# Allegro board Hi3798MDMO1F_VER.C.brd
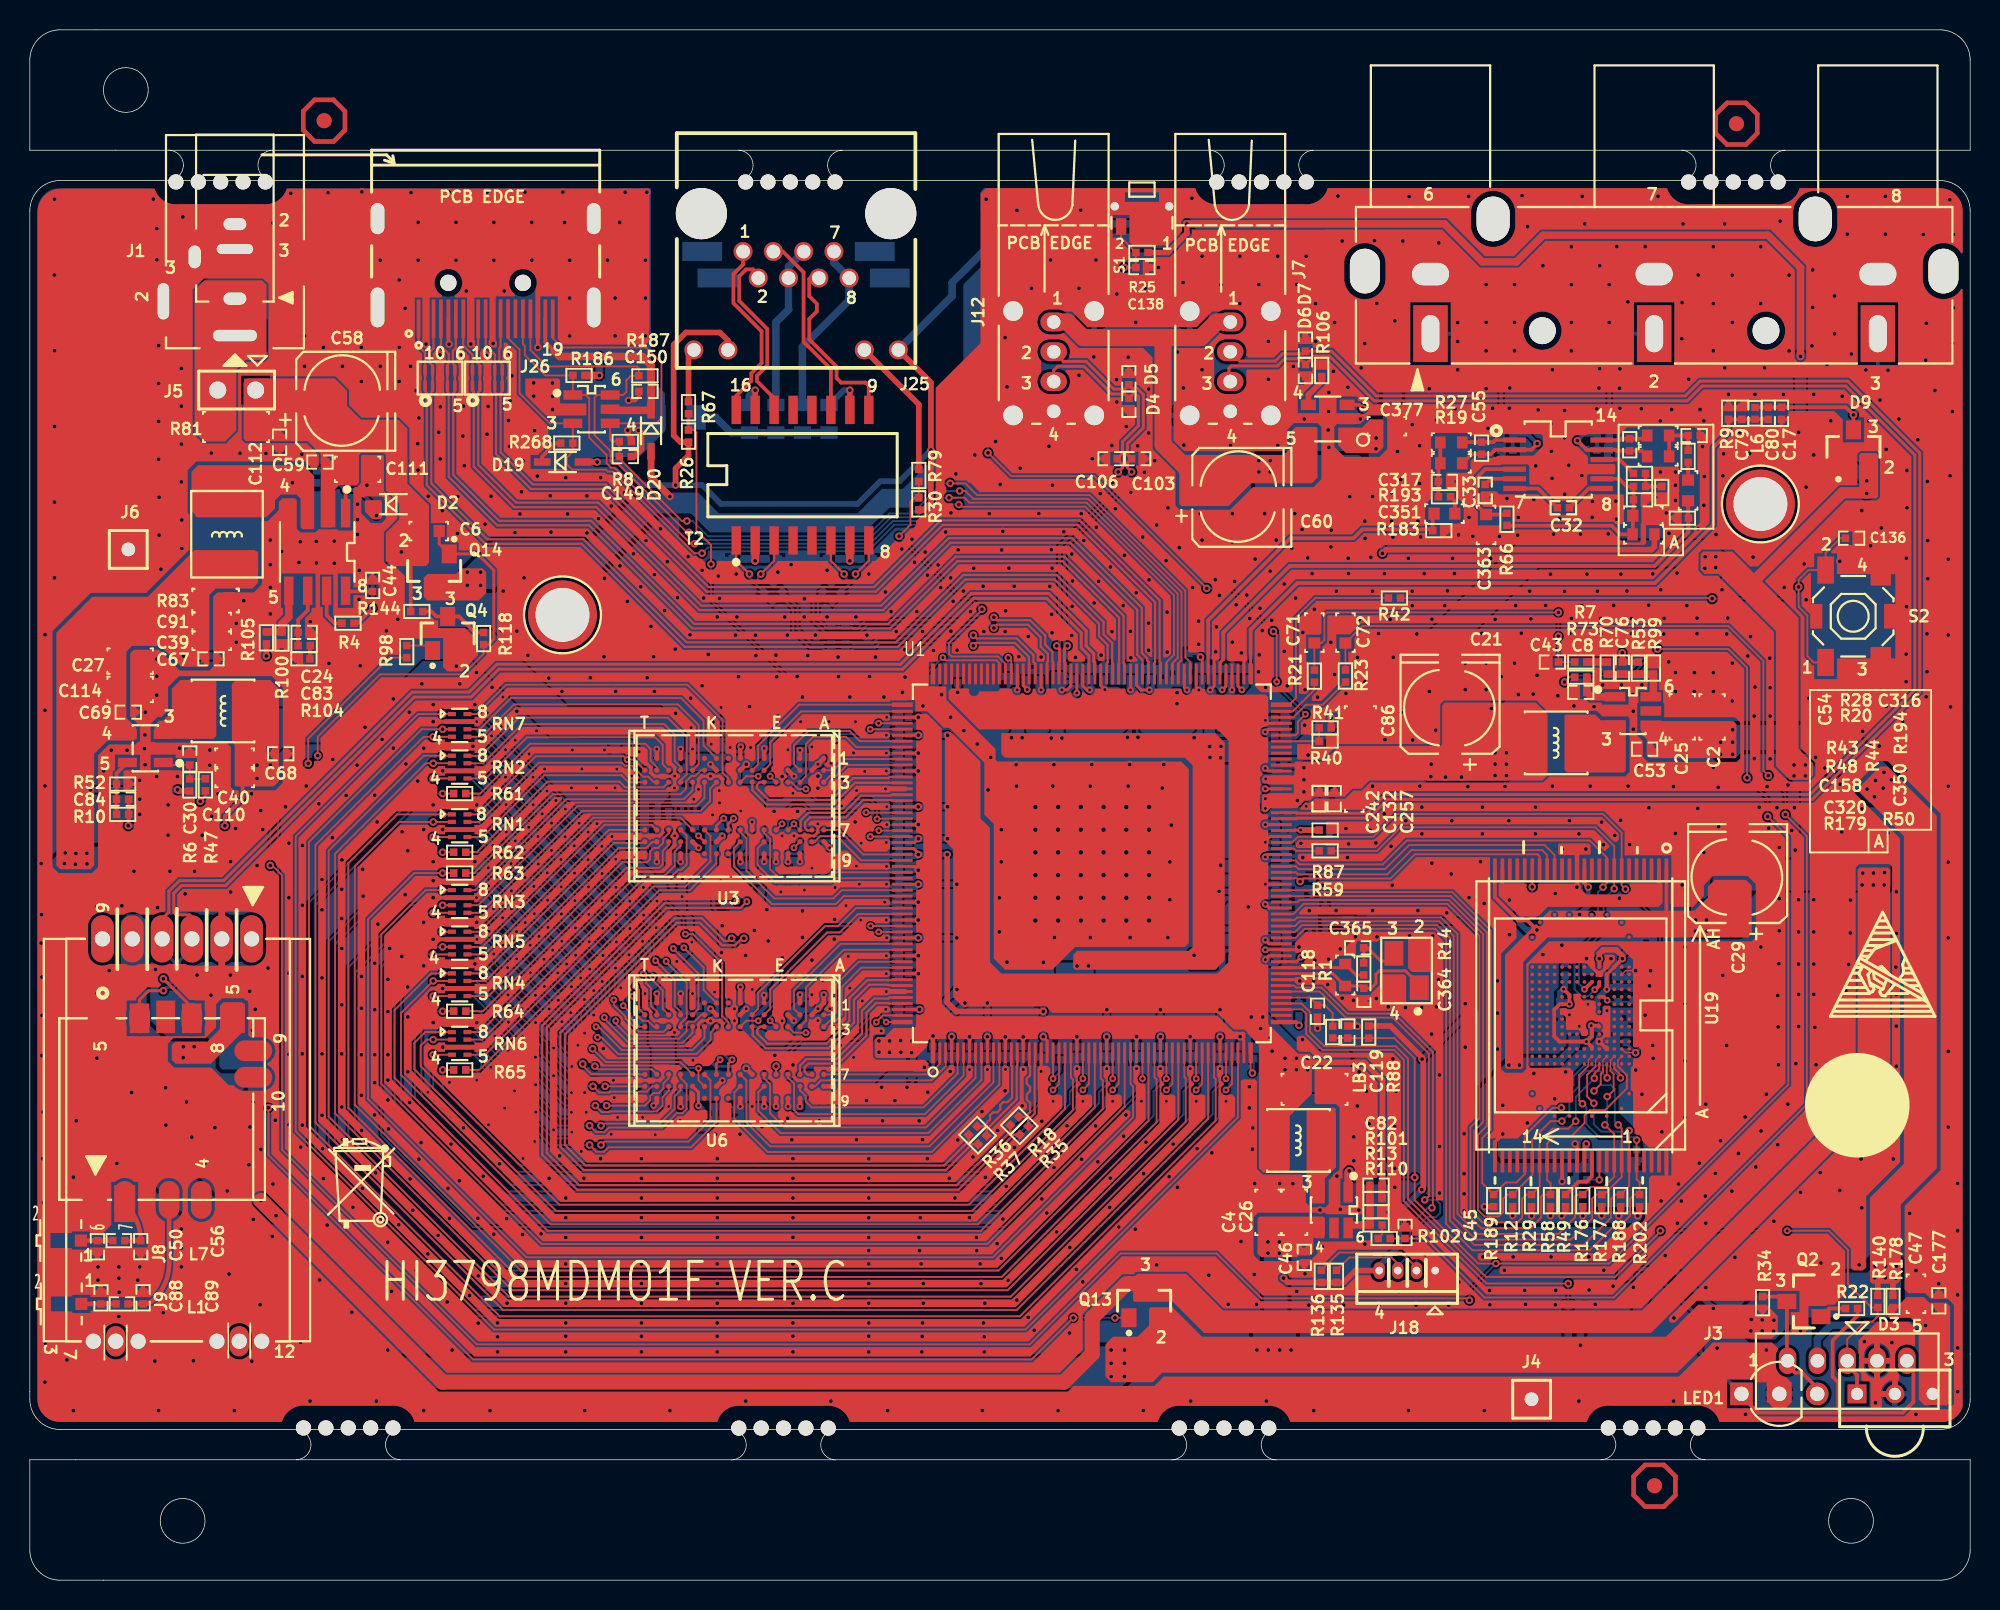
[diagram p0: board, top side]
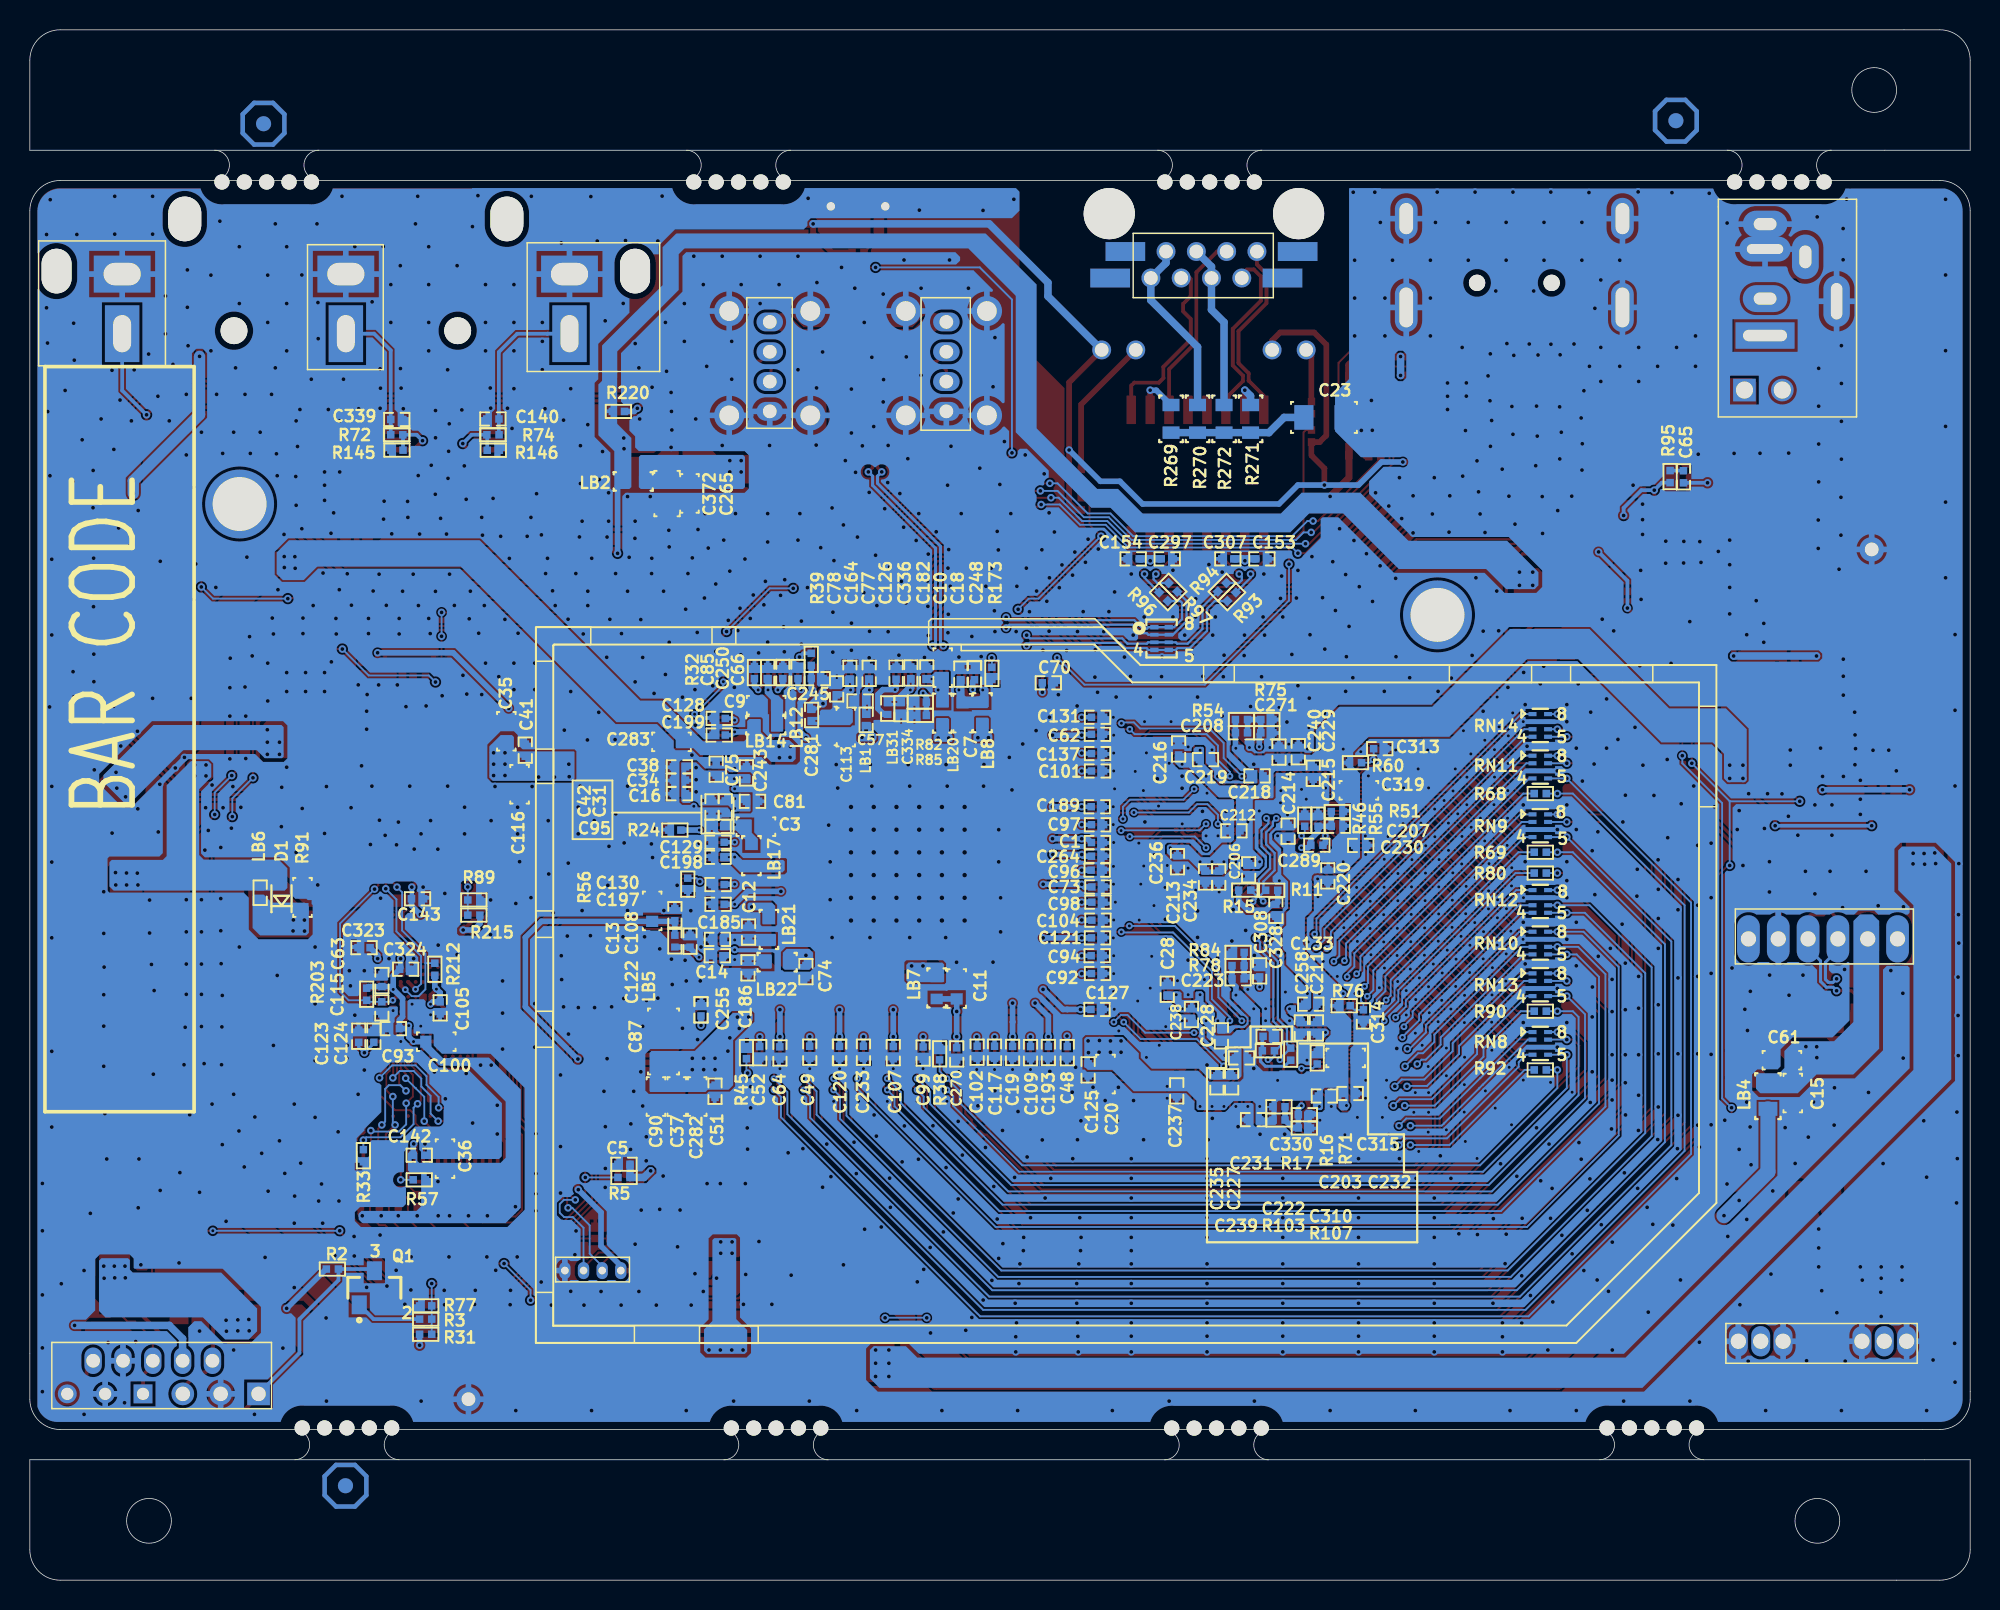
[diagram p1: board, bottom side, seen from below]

Outline 130.13 x 104.03 mm; copper layers: TOP, BOTTOM. Coordinates in mm from the lower left corner of the outline.
Outline path: circle c6.44,99.99 r1.5 ; circle c10.25,3.98 r1.5 ; circle c122.14,3.98 r1.5 ; 0,102 arc(0.6,103.44) 2.03,104.03 128.1,104.03 arc(129.53,103.44) 130.13,102 130.13,95.95 0,95.95 0,102 ; 0,91.89 arc(0.6,93.33) 2.03,93.92 128.1,93.92 arc(129.53,93.33) 130.13,91.89 130.13,12.14 arc(129.53,10.71) 128.1,10.11 2.03,10.11 arc(0.6,10.71) 0,12.14 0,91.89 ; 0,8.08 130.13,8.08 130.13,2.03 arc(129.53,0.6) 128.1,0 2.03,0 arc(0.6,0.6) 0,2.03 0,8.08

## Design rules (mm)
constraint set DEFAULT: min track width 0.127
net group $4N904: nets $4N904 $4N905
net group $6N188: nets $6N188 XOUT
net group $6N2411: nets $6N2411 USB_BOOT
net group $8N1694: nets $8N1694 DDR_CLK0P
net group $8N1695: nets $8N1695 DDR_CLK0N
net group $8N1696: nets $8N1696 DDR_CLK1P
net group $8N1697: nets $8N1697 DDR_CLK1N
net group $13N803: nets 5V0_MOS $13N803
net group $14N721: nets $14N721 LED_RED
net group $14N731: nets $14N731 LED_CTRL
net group $15N1021: nets $15N1021 $15N1025
net group $15N1022: nets $15N1022 $15N1029
net group $15N1031: nets $15N1031 $15N1032
net group $15N1036: nets $15N1036 $15N1037
net group $16N1066: nets $16N1066 LED0_BASE
net group $16N1067: nets $16N1067 LED0_LINK_ACT
net group $18N796: nets $18N796 HDMI_TX_CEC
net group CLK: nets NF_RDY0_EMMC_RST NF_REN_EMMC_CLK
net group CVBS: nets CVBS CVBS_OUT
net group DIFF: nets TX+_PHY0 TX-_PHY0
net group DIFF90: nets USB2_DM USB2_DP
net group DIFFPAIR1: nets RX+_PHY0 RX-_PHY0
net group 01: nets ADAC_VOUTL ADAC_VOUTR AUDIO_L AUDIO_R
net group 5V0_MOS_HDMI: nets 5V0_MOS_HDMI HDMI_TX_SCL HDMI_TX_SDA
net group $4N593: nets $4N593 $4N687 $4N724 $5N549 STANDBY_PWROFF
net group $4N676: nets 1V1_CPU $4N676 $4N677 $4N894 CPU_CTRL
net group $4N714: nets $4N714 $4N715 $4N716 CORE_CTRL
net group $4N903: nets $4N903 $4N923 $4N925
net group $4N906: nets 5V0 $4N906 $4N944 $5N541 $5N542
net group $15N1074: nets $15N1074 $15N1075 $15N1114 VDD_AUDIO
net group DDR-ADD: nets DDR_ADDR0 DDR_ADDR0_A DDR_ADDR0_B DDR_ADDR1 DDR_ADDR1_A DDR_ADDR1_B DDR_ADDR2 DDR_ADDR2_A DDR_ADDR2_B DDR_ADDR3 DDR_ADDR3_A DDR_ADDR3_B DDR_ADDR4 DDR_ADDR4_A DDR_ADDR4_B DDR_ADDR5 DDR_ADDR5_A DDR_ADDR5_B DDR_ADDR6 DDR_ADDR6_A DDR_ADDR6_B DDR_ADDR7 DDR_ADDR7_A DDR_ADDR7_B DDR_ADDR8 DDR_ADDR8_A DDR_ADDR8_B DDR_ADDR9 DDR_ADDR9_A DDR_ADDR9_B DDR_ADDR10 DDR_ADDR10_A DDR_ADDR10_B DDR_ADDR11 DDR_ADDR11_A DDR_ADDR11_B DDR_ADDR12 DDR_ADDR12_A DDR_ADDR12_B DDR_ADDR13 DDR_ADDR13_A DDR_ADDR13_B DDR_ADDR14 DDR_ADDR14_A DDR_ADDR14_B DDR_ADDR15 DDR_ADDR15_A DDR_ADDR15_B DDR_BA0 DDR_BA0_A DDR_BA0_B DDR_BA1 DDR_BA1_A DDR_BA1_B DDR_BA2 DDR_BA2_A DDR_BA2_B DDR_CASN DDR_CASN_A DDR_CASN_B DDR_CKE DDR_CKE_A DDR_CKE_B DDR_CSN DDR_CSN_A DDR_CSN_B DDR_ODT DDR_ODT_A DDR_ODT_B DDR_PLL DDR_RASN DDR_RASN_A DDR_RASN_B DDR_RESETN DDR_RESETN_A DDR_RESETN_B DDR_VREF_CA_A DDR_VREF_CA_B DDR_VREF_DQ_A DDR_VREF_DQ_B DDR_WEN DDR_WEN_A DDR_WEN_B
net group DDR-DATA: nets DDR_DM0 DDR_DM1 DDR_DM2 DDR_DM3 DDR_DQ0 DDR_DQ1 DDR_DQ2 DDR_DQ3 DDR_DQ4 DDR_DQ5 DDR_DQ6 DDR_DQ7 DDR_DQ8 DDR_DQ9 DDR_DQ10 DDR_DQ11 DDR_DQ12 DDR_DQ13 DDR_DQ14 DDR_DQ15 DDR_DQ16 DDR_DQ17 DDR_DQ18 DDR_DQ19 DDR_DQ20 DDR_DQ21 DDR_DQ22 DDR_DQ23 DDR_DQ24 DDR_DQ25 DDR_DQ26 DDR_DQ27 DDR_DQ28 DDR_DQ29 DDR_DQ30 DDR_DQ31
net group DIFF100: nets HDMI_TX0N HDMI_TX0P HDMI_TX1N HDMI_TX1P HDMI_TX2N HDMI_TX2P HDMI_TXCN HDMI_TXCP
net group DQS: nets DDR_DQS0N DDR_DQS0P DDR_DQS1N DDR_DQS1P DDR_DQS3N DDR_DQS3P
net group GND: nets GND
net group POWER: nets 1V1_CORE 1V5_DDR3 3V3 3V3_MOS
net group USB: nets USB0_DM USB0_DP USB1_DM USB1_DP

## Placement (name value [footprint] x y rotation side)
C1  100NF  [SC0402]  58.53 49.5 180 bottom
C2  10UF  [SC0805]  112.82 57.93 90 top
C3  1UF  [SC0603]  81.43 50.56 180 bottom
C4  10UF  [SC0805]  83.04 24.68 90 top
C5  220NF  [SC0402]  90.28 27.91 0 bottom
C6  220NF  [SC0603]  26.75 70.39 0 top
C7  1UF  [SC0603]  67.56 58.18 270 bottom
C8  220NF  [SC0402]  104.01 59.58 180 top
C9  1UF  [SC0603]  80.75 58.72 0 bottom
C10  1UF  [SC0603]  68.91 61.23 90 bottom
C11  1UF  [SC0603]  67.97 39.7 90 bottom
C12  1UF  [SC0402]  81.93 43.49 90 bottom
C13  1UF  [SC0603]  88.39 44.91 90 bottom
C14  1UF  [SC0402]  84.02 41.9 0 bottom
C15  10UF  [SC0603]  11.9 32.69 270 bottom
C16  100NF  [SC0402]  86.56 52.77 0 bottom
C17  180PF  [SC0402]  117.48 78.3 270 top
C18  10NF/NC  [SC0402]  67.69 60.8 90 bottom
C19  470NF  [SC0402]  64.22 35.41 270 bottom
C20  10UF/NC  [SC0603]  57.99 33.96 270 bottom
C21  100UF  [SAC6666]  95.25 58.78 90 top
C22  47UF/NC  [SC1206]  86.16 32.94 0 top
C23  1NF  [SC1206]  43.34 78.02 180 bottom
C24  47PF/NC  [SC0402]  18.4 63.6 0 top
C25  10UF  [SC0805]  110.81 57.93 90 top
C26  10UF/NC  [SC0805]  84.82 24.68 90 top
C27  10UF/NC  [SC0805]  6.73 61.67 0 top
C28  100NF  [SC0402]  53.85 39.65 90 bottom
C29  100UF/NC  [SAC6666]  114.53 47.42 90 top
C30  220NF  [SC0402]  10.73 55.11 90 top
C31  2.2UF  [HSC0402]  83.49 51.88 270 bottom
C32  330N  [HSC0402]  102.85 71.96 0 top
C33  330N  [HSC0402]  97.6 73.12 90 top
C34  100NF  [SC0402]  86.56 53.69 0 bottom
C35  10UF  [SC0603]  98.17 56.96 90 bottom
C36  1UF/NC  [SC0603]  102.29 28.29 90 bottom
C37  10UF  [SC0603]  86.74 32.45 270 bottom
C38  100NF  [SC0402]  86.56 54.58 0 bottom
C39  10UF  [SC0603]  12.2 63.03 0 top
C40  10UF  [SC0603]  13.73 55.19 180 top
C41  100NF  [SC0402]  96.9 55.69 90 bottom
C42  100NF  [SC0402]  84.38 51.88 270 bottom
C43  100NF/NC  [SC0402]  102.11 61.61 180 top
C44  100NF  [SC0402]  22.99 66.75 90 top
C45  100NF/NC  [SC0402]  92.23 23.34 90 top
C46  100NF  [SC0402]  85.47 21.66 270 top
C47  10UF  [SC0603]  126.49 19.22 90 top
C48  100NF  [SC0402]  60.55 35.4 270 bottom
C49  100NF  [SC0402]  77.83 35.43 270 bottom
C50  1PF/NC  [SC0402]  4.53 22.38 270 top
C51  100NF  [SC0402]  84.18 32.81 270 bottom
C52  100NF  [SC0402]  81.18 35.4 270 bottom
C53  100NF  [SC0402]  108.3 55.76 180 top
C54  47PF  [SC0402]  107.29 76.19 90 top
C55  47PF  [SC0402]  97.36 75.96 270 top
C56  1PF/NC  [SC0402]  7.44 22.38 270 top
C57  100NF/NC  [SC0402]  74.45 59 0 bottom
C58  100UF  [SAC6666]  21.18 79.11 0 top
C59  100NF  [SC0402]  19.46 75.03 180 top
C60  100UF  [SAC6666]  81.28 72.66 0 top
C61  100NF  [SC0603]  12.62 34.89 0 bottom
C62  100NF  [SC0402]  58.53 56.76 180 bottom
C63  100NF/NC  [SC0402]  106.51 40.24 90 bottom
C64  100NF  [SC0402]  79.82 35.38 270 bottom
C65  10NF  [SC0402]  19.23 74.04 270 bottom
C66  100NF  [SC0402]  78.61 60.9 90 bottom
C67  100NF  [SC0402]  12.15 61.83 0 top
C68  100NF  [SC0402]  16.83 55.46 0 top
C69  100NF  [SC0402]  6.6 58.24 0 top
C70  100NF  [SC0402]  61.82 60.22 180 bottom
C71  2.2UF  [SC0603]  86.15 63.59 90 top
C72  2.2UF  [SC0603]  88.23 63.59 90 top
C73  100NF  [SC0402]  58.5 46.52 180 bottom
C74  100NF/NC  [SC0402]  78.08 40.84 270 bottom
C75  100NF  [SC0402]  84.1 54.42 90 bottom
C76  22PF  [SC0402]  106.8 61.2 90 top
C77  1UF  [SC0402]  73.84 60.85 90 bottom
C78  100NF/NC  [SC0402]  76.02 59.81 90 bottom
C79  180PF  [SC0402]  114.81 78.3 90 top
C80  100PF  [SC0402]  116.59 78.3 90 top
C81  100NF  [SC0402]  81.66 52.27 180 bottom
C82  22PF  [SC0402]  90.28 26.5 0 top
C83  3.3NF  [SC0402]  18.4 62.72 0 top
C84  22PF  [SC0402]  6.22 52.4 0 top
C85  100NF/NC  [SC0402]  80.65 60.9 90 bottom
C86  22UF/NC  [SC1206]  89.23 56.43 90 top
C87  22UF/NC  [SC1206]  87.63 36.15 90 bottom
C88  1PF/NC  [SC0402]  4.77 18.94 90 top
C89  1PF/NC  [SC0402]  7.6 18.95 90 top
C90  10UF  [SC0603]  88.14 32.45 270 bottom
C91  10UF  [SC0603]  12.2 64.3 0 top
C92  1UF  [SC0402]  58.52 40.71 180 bottom
C93  100NF/NC  [SC0402]  105.75 37.01 0 bottom
C94  1UF/NC  [SC0402]  58.55 41.9 180 bottom
C95  100NF/NC  [SC0402]  83.97 50.59 0 bottom
C96  1UF  [SC0402]  58.55 47.65 180 bottom
C97  470NF  [SC0402]  58.52 50.69 180 bottom
C98  100NF  [SC0402]  58.5 45.5 180 bottom
C99  100NF/NC  [SC0402]  70.22 35.37 270 bottom
C100  2.2UF  [SC0603]  102.87 36.14 180 bottom
C101  100NF  [SC0402]  58.52 54.3 180 bottom
C102  100NF  [SC0402]  66.6 35.43 270 bottom
C103  3PF/NC  [SC0402]  74.3 75.25 0 top
C104  100NF  [SC0402]  58.5 44.29 180 bottom
C105  100NF  [SC0402]  102.61 38.4 270 bottom
C106  3PF/NC  [SC0402]  72.52 75.25 180 top
C107  100NF  [SC0402]  72.22 35.4 270 bottom
C108  100NF/NC  [SC0402]  86.87 44.66 90 bottom
C109  470NF  [SC0402]  63.02 35.4 270 bottom
C110  10UF  [SC0603]  13.74 53.83 180 top
C111  10UF  [SC0805]  21.98 74.54 0 top
C112  100NF  [SC0402]  16.75 76.36 270 top
C113  2.2UF/NC  [SC0603]  75.41 57.24 270 bottom
C114  10UF  [SC0805]  6.73 59.77 0 top
C115  1NF/NC  [SC0402]  106.52 38.4 270 bottom
C116  10UF  [SC0603]  97.28 53.41 270 bottom
C117  470NF  [SC0402]  65.43 35.43 270 bottom
C118  100NF/NC  [SC0402]  86.36 38.18 270 top
C119  100NF/NC  [SC0402]  88.39 36.78 90 top
C120  2.2UF  [HSC0402]  75.82 35.41 270 bottom
C121  100NF  [SC0402]  58.53 43.1 180 bottom
C122  100NF/NC  [SC0402]  85.85 42.88 90 bottom
C123  100NF  [SC0402]  108.07 36.5 90 bottom
C124  100NF  [SC0402]  107.05 36.5 90 bottom
C125  100NF/NC  [SC0402]  59.16 34.24 270 bottom
C126  100NF  [SC0402]  72.03 60.86 90 bottom
C127  100NF  [SC0402]  58.56 38.3 180 bottom
C128  100NF  [SC0402]  83.9 57.83 0 bottom
C129  100NF  [SC0402]  83.97 49.52 0 bottom
C130  100NF  [SC0402]  83.97 46.68 0 bottom
C131  100NF/NC  [SC0402]  58.52 57.9 180 bottom
C132  1UF  [SC0402]  87.48 52.44 270 top
C133  100NF  [SC0402]  44.22 38.65 0 bottom
C136  100NF  [SC0402]  122.17 69.92 0 top
C137  100NF  [SC0402]  58.52 55.47 180 bottom
C138  100NF  [SC0402]  74.58 88.08 180 top
C140  1NF  [SC0402]  99.07 77.92 0 bottom
C142  100NF/NC  [SC0402]  104.01 28.52 180 bottom
C143  100NF/NC  [SC0402]  104.13 45.72 180 bottom
C149  100NF  [SC0402]  39.93 75.4 0 top
C150  100NF  [SC0402]  41.26 79.77 180 top
C153  100NF  [SC0402]  47.5 68.53 180 bottom
C154  100NF  [SC0402]  56.13 68.53 0 bottom
C158  100NF  [SC0402]  107.95 72.49 0 top
C164  10NF  [SC0402]  75.13 60.85 90 bottom
C177  100NF/NC  [SC0402]  128.02 18.75 90 top
C182  10NF/NC  [SC0402]  69.98 60.88 90 bottom
C185  10NF  [SC0402]  84.01 43 0 bottom
C186  10NF  [SC0402]  81.97 41.09 270 bottom
C189  1UF  [SC0402]  58.54 51.9 180 bottom
C193  1UF  [SC0402]  61.82 35.41 270 bottom
C197  100NF  [SC0402]  83.97 45.35 0 bottom
C198  100NF  [SC0402]  83.97 48.51 0 bottom
C199  100NF  [SC0402]  83.9 56.71 0 bottom
C203  100NF  [SC0402]  43.31 32.49 180 bottom
C206  100NF/NC  [SC0402]  48.39 47.67 270 bottom
C207  100NF  [SC0402]  42.44 50.59 0 bottom
C208  100NF  [SC0402]  48.87 56.86 180 bottom
C211  100NF/NC  [SC0402]  43.84 37.05 270 bottom
C212  100NF  [SC0402]  49.38 50.28 0 bottom
C213  100NF  [SC0402]  51.28 47.19 270 bottom
C214  100NF  [SC0402]  45.75 50.26 90 bottom
C215  100NF/NC  [SC0402]  44.06 54.15 270 bottom
C216  100NF/NC  [SC0402]  53.09 55.78 90 bottom
C218  100NF/NC  [SC0402]  47.83 53.97 0 bottom
C219  100NF  [SC0402]  51.28 55.06 180 bottom
C220  100NF/NC  [SC0402]  43.08 47.26 270 bottom
C222  100NF  [SC0402]  46.36 31.77 180 bottom
C223  100NF  [SC0402]  49.1 40.35 180 bottom
C227  100NF/NC  [SC0402]  49.53 33.44 90 bottom
C228  100NF  [SC0402]  50.22 36.53 90 bottom
C229  100NF/NC  [SC0402]  45.06 55.59 90 bottom
C230  100NF  [SC0402]  40.87 49.3 180 bottom
C231  100NF/NC  [SC0402]  48.87 35.04 0 bottom
C232  100NF/NC  [SC0402]  41.58 32.66 180 bottom
C233  100NF/NC  [SC0402]  74.22 35.43 270 bottom
C234  100NF/NC  [SC0402]  50.39 47.19 270 bottom
C235  100NF  [SC0402]  50.52 33.44 90 bottom
C236  100NF/NC  [SC0402]  53.16 48.21 270 bottom
C237  100NF/NC  [SC0402]  53.21 32.83 270 bottom
C238  100NF/NC  [SC0402]  52.22 37.96 270 bottom
C239  100NF  [SC0402]  48.06 30.9 0 bottom
C240  100NF/NC  [SC0402]  46.36 55.57 90 bottom
C242  2.2UF  [HSC0402]  86.46 52.44 270 top
C243  470NF  [SC0402]  82.07 54.17 90 bottom
C245  100NF  [SC0402]  77.32 60.5 180 bottom
C248  2.2UF  [HSC0402]  66.78 60.83 90 bottom
C250  2.2UF  [HSC0402]  79.63 60.9 270 bottom
C255  2.2UF  [HSC0402]  85.12 38.27 270 bottom
C257  10UF  [SC0603]  88.82 52.85 270 top
C258  100NF/NC  [SC0402]  44.86 37.05 270 bottom
C264  10NF/NC  [SC0402]  58.52 48.58 180 bottom
C265  100NF/NC  [SC0603]  85.89 72.93 270 bottom
C270  10NF  [SC0402]  67.97 35.31 270 bottom
C271  1UF  [SC0402]  47.17 56.86 180 bottom
C281  10UF  [SC0603]  76.63 57.32 270 bottom
C282  10UF  [SC0603]  85.37 32.45 270 bottom
C283  2.2UF  [SC0603]  87.1 56.25 0 bottom
C289  1UF  [SC0402]  43.81 49.32 180 bottom
C297  10NF/NC  [SC0402]  53.85 68.53 180 bottom
C307  10NF/NC  [SC0402]  49.78 68.53 0 bottom
C308  1UF  [SC0402]  47.65 40.89 90 bottom
C310  1UF  [SC0402]  44.65 31.23 180 bottom
C313  1NF  [SC0402]  39.6 55.8 180 bottom
C314  1NF  [SC0402]  40.69 37.86 270 bottom
C315  10UF/NC  [SC0603]  41.88 35.04 180 bottom
C316  680PF  [SC0402]  111.62 76.81 0 top
C317  680PF  [SC0402]  94.87 73.73 0 top
C319  10UF/NC  [SC0603]  41 53 180 bottom
C320  10UF  [SC0603]  108.21 71.43 0 top
C323  100NF/NC  [SC0402]  107.72 42.44 0 bottom
C324  100NF/NC  [SC0402]  104.92 41 180 bottom
C328  10NF  [SC0402]  46.56 44.95 270 bottom
C330  10NF  [SC0402]  47.02 36.49 180 bottom
C334  1UF  [SC0402]  71.7 58.49 270 bottom
C336  10NF/NC  [SC0402]  71.04 60.88 90 bottom
C339  1NF  [SC0402]  105.52 77.89 180 bottom
C350  2.2UF  [SC0603]  111.21 73.13 270 top
C351  2.2UF  [SC0603]  94.87 71.57 0 top
C363  10UF  [SC0603]  97.66 70.81 270 top
C364  30PF  [SC0402]  89.46 39.31 270 top
C365  30PF  [SC0402]  89.05 42.44 180 top
C372  10UF/NC  [SC0805]  87.39 72.91 270 bottom
C377  100NF  [SC0603]  91.01 77.43 0 top
D1  NC  [HSOD323A]  113.25 45.73 270 bottom
D2  NC  [HSOD323A]  24.38 72.2 180 top
D3  IR  [SEN3-100C]  125.08 12.5 0 top
D4  NC  [SC0402]  73.71 78.91 270 top
D5  NC  [SC0402]  73.71 80.62 90 top
D6  NC  [SC0402]  85.55 81.17 270 top
D7  NC  [SC0402]  85.55 82.87 90 top
D9  D2-3_A  [SOT23]  122.3 76.05 0 top
D19  D_A  [HSOD323A]  35.73 75.03 180 top
D20  D_A  [HSOD323A]  41.66 77.13 90 top
ID1  PCB_MARKPOINT_A  [ID-BOARD]  19.74 97.94 0 top
ID2  PCB_MARKPOINT_A  [ID-BOARD]  114.45 97.73 0 top
ID3  PCB_MARKPOINT_A  [ID-BOARD]  19.74 97.94 180 bottom
ID4  PCB_MARKPOINT_A  [ID-BOARD]  108.96 6.34 180 bottom
ID5  PCB_MARKPOINT_A  [ID-BOARD]  114.45 97.73 180 bottom
ID6  PCB_MARKPOINT_A  [ID-BOARD]  108.96 6.34 0 top
J1  DC_012_HW  [PWC3-RF-A]  13.76 83.52 90 top
J2  WIFI_2T2R  [SIP12-2_0MM-1827]  9.87 29.53 270 top
J3  NC  [SIP5-2MM]  117.88 14.72 0 top
J4  NC  [SIP-1P]  100.71 12.14 0 top
J5  NC  [SIP-2P]  13.87 79.86 180 top
J6  NC  [SIP-1P]  6.6 69.17 0 top
J7  UB31123_K1_4F  [USB4-200-1907]  80.5 84.43 270 top
J8  NC  [HSCOX-AMC-TM-A]  2.08 22.79 270 top
J9  NC  [HSCOX-AMC-TM-A]  2.11 18.54 270 top
J10  NC  [DC-002]  13.75 86 0 top
J12  UB31123_K1_4F  [USB4-200-1907]  68.66 84.43 270 top
J18  SDW12501_4A_HW  [WBC0104-49T]  94.25 20.78 180 top
J25  406533_1  [MJ8-RLY]  47.83 89.16 0 top
J26  0  [WBC0119-20R-A]  30.57 89.8 180 top
J34  AV_JACK  [AV3-8-5-1]  108.94 86.89 270 top
L1  1NH/NC  [SL0402]  6.18 18.54 0 top
L2  3.3UH  [SWPA4020S]  102.36 56.19 180 top
L3  3.3UH  [SWPA4020S]  85.08 29.51 180 top
L4  3.3UH  [SWPA4020S]  12.95 58.33 0 top
L5  6.8UH  [SWPA5040S]  13.22 70.18 270 top
L6  220NH  [SL0402]  115.7 78.3 90 top
L7  1NH/NC  [SL0402]  5.97 22.78 0 top
LB1  0  [SL0402]  74.04 57.73 270 bottom
LB2  NC  [SL0603]  89.66 73.73 0 bottom
LB3  BLM15BD601SN1D  [SL0402]  87.38 36.78 270 top
LB4  MGLB2012_220T_LF  [SL0805]  13.56 32.48 270 bottom
LB5  BLM15BD601SN1D  [SL0402]  86.87 42.88 270 bottom
LB6  BLM15BD601SN1D  [SL0402]  114.68 46.13 270 bottom
LB7  BLM18HG601SN1D  [SL0603]  69.31 39.74 90 bottom
LB8  0  [SL0603]  66.24 58.21 270 bottom
LB12  BLM15HG102SN1D  [SL0402]  77.7 58.06 90 bottom
LB14  0  [SL0603]  80.77 57.37 180 bottom
LB17  0  [SL0603]  81.74 48.62 90 bottom
LB20  0  [SL0603]  68.94 58.18 90 bottom
LB21  BLM18HG601SN1D  [SL0603]  80.56 43.67 270 bottom
LB22  BLM18HG601SN1D  [SL0603]  80.01 41.47 0 bottom
LB31  0  [SL0402]  72.59 58.49 90 bottom
LED1  209_3SYGSURC_S530_A3HW  [LED3C-100C]  114.79 12.5 0 top
M20  RIVET_HOLE162_R4_A  [HOLE182-142]  35.72 64.78 0 top
M21  RIVET_HOLE162_R4_A  [HOLE182-142]  116.06 72.21 0 top
NOREF  -  []  24.77 26.75 0 top
NOREF#2  -  []  52.15 146.41 0 top
NOREF#3  -  [unnamed#2]  50.55 9.08 0 top
NOREF#4  -  []  123.57 40.84 0 top
NOREF#5  -  [unnamed#2]  82.6 94.95 180 top
NOREF#6  -  []  -138.05 -170.86 0 top
NOREF#7  -  [unnamed#2]  21.35 9.09 0 top
NOREF#8  -  [unnamed#2]  12.8 94.96 180 top
NOREF#9  -  [unnamed#2]  114.24 94.95 180 top
NOREF#10  -  [unnamed#2]  51 94.95 180 top
NOREF#11  -  []  123.06 32.1 0 top
NOREF#12  -  []  -49.43 144.62 0 top
NOREF#13  -  [unnamed#2]  80.08 9.08 0 top
NOREF#14  -  []  0 8.08 0 top
NOREF#15  -  []  1.84 0 90 top
NOREF#16  -  []  139.4 156.72 0 top
NOREF#17  -  [unnamed#2]  108.86 9.09 0 top
NOREF#18  -  []  79.46 0.7 180 bottom
Q1  NPN-BEC  [SOT23]  107.02 19.62 180 bottom
Q2  NPN-BEC  [SOT23]  118.98 18.7 90 top
Q4  NPN-BEC  [SOT23]  28.02 63.53 0 top
Q13  PMOS-GSD  [SOT23]  74.73 18.75 0 top
Q14  PMOS-GSD  [SOT23]  27.11 67.72 180 top
R1  1MEG  [SR0603]  88.21 40.61 270 top
R2  330  [SR0402]  109.84 20.88 180 bottom
R3  1K  [SR0402]  103.58 17.52 0 bottom
R4  100K  [SR0402]  21.34 64.21 180 top
R5  20K  [SR0402]  90.28 27.03 180 bottom
R6  47K  [SR0402]  10.72 53.36 90 top
R7  51K  [SR0402]  104.01 61.61 180 top
R8  47K  [SR0402]  39.93 76.41 180 top
R9  75  [SR0402]  113.92 78.3 90 top
R10  150K  [SR0402]  6.22 51.39 0 top
R11  100  [SR0402]  46.84 46.3 180 bottom
R12  47K  [SR0402]  99.44 25.47 90 top
R13  13.7K  [SR0402]  90.28 24.72 180 top
R14  0  [SR0402]  89.46 41.01 90 top
R15  100  [SR0402]  48.65 46.31 180 bottom
R16  100  [SR0402]  45.57 35.3 270 bottom
R17  100  [SR0402]  47.07 35.53 180 bottom
R18  0  [SR0402]  66.04 30.81 45 top
R19  75K  [SR0603]  95.33 74.95 0 top
R20  75K  [SR0603]  109.2 75.41 0 top
R21  1K  [SR0402]  86.15 60.66 270 top
R22  10K  [SR0402]  122.17 18.23 180 top
R23  1K  [SR0402]  88.23 60.67 270 top
R24  270  [SR0402]  86.87 50.34 180 bottom
R25  10K  [SR0402]  74.58 89.1 180 top
R26  4.7K  [SR0402]  44.18 76.77 90 top
R27  5.1K  [SR0603]  95.33 76.34 0 top
R28  5.1K  [SR0603]  109.2 76.81 0 top
R29  47K  [SR0402]  100.71 25.47 90 top
R30  4.7K  [SR0402]  59.62 72.22 90 top
R31  4.7K/NC  [SR0402]  103.58 16.5 180 bottom
R32  12K  [SR0402]  81.53 60.9 270 bottom
R33  10K/NC  [SR0402]  107.76 28.48 270 bottom
R34  330  [SR0402]  116.2 18.62 90 top
R35  0  [SR0402]  66.67 30.18 45 top
R36  0  [SR0402]  63.25 30.18 45 top
R37  0  [SR0402]  63.88 29.54 45 top
R38  10K/NC  [SR0402]  69.11 35.32 270 bottom
R39  10K  [SR0402]  77.72 61.79 270 bottom
R40  10K/NC  [SR0402]  86.87 56.3 0 top
R41  10K  [SR0402]  86.87 57.19 0 top
R42  1K  [SR0402]  91.52 65.91 180 top
R43  0  [SR0402]  107.95 74.27 0 top
R44  2.2K  [SR0402]  109.45 72.99 270 top
R45  240  [SR0402]  82.07 35.4 90 bottom
R46  240  [SR0402]  44.63 51 270 bottom
R47  20K/NC  [SR0402]  11.78 53.37 90 top
R48  5.6K  [SR0402]  107.95 73.38 0 top
R49  0/NC  [SR0402]  103 25.47 90 top
R50  470K  [SR0402]  110.83 71.27 180 top
R51  1K  [SR0402]  42.44 51.58 0 bottom
R52  100K  [SR0402]  6.22 53.42 0 top
R53  15K  [SR0402]  107.87 61.2 90 top
R54  1K  [SR0402]  48.87 57.75 180 bottom
R55  1K  [SR0402]  43.74 51 90 bottom
R56  10K  [SR0402]  86 46.7 90 bottom
R57  0/NC  [SR0402]  104.01 26.87 180 bottom
R58  47K  [SR0402]  101.98 25.47 90 top
R59  33  [SR0402]  86.87 48.94 180 top
R60  10K  [SR0402]  41.22 54.86 180 bottom
R61  33  [SR0402]  28.83 52.78 0 top
R62  33  [SR0402]  28.83 48.85 0 top
R63  33  [SR0402]  28.83 47.45 0 top
R64  33  [SR0402]  28.83 38.18 0 top
R65  33  [SR0402]  28.83 34.24 0 top
R66  470K  [SR0402]  99.06 71.19 270 top
R67  330  [SR0402]  44.18 78.68 270 top
R68  33  [SR0402]  28.83 52.78 0 bottom
R69  33  [SR0402]  28.83 48.85 0 bottom
R70  33K  [SR0402]  105.79 61.2 90 top
R71  240  [SR0402]  43.79 35.04 270 bottom
R72  560  [HSR0402]  105.52 76.86 0 bottom
R73  20K  [SR0402]  104.01 60.59 0 top
R74  560  [HSR0402]  99.07 76.86 0 bottom
R75  1K  [SR0402]  47.17 57.75 180 bottom
R76  10K  [SR0402]  41.99 38.55 180 bottom
R77  4.7K  [SR0402]  103.58 18.41 0 bottom
R78  1K  [SR0402]  49.1 41.24 180 bottom
R79  330  [SR0402]  59.62 74.13 270 top
R80  33  [SR0402]  28.83 47.45 0 bottom
R81  0  [SR1206]  13.83 77.38 0 top
R82  270  [SR0402]  70.41 58.92 180 bottom
R83  2K/NC  [SR0805]  12.46 65.73 0 top
R84  1K  [SR0402]  49.1 42.13 0 bottom
R85  270  [SR0402]  70.41 58.03 180 bottom
R87  270  [SR0402]  86.87 50.34 180 top
R88  1K  [SR0402]  89.79 36.78 90 top
R89  1K/NC  [SR0402]  100.35 45.64 180 bottom
R90  33  [SR0402]  28.83 38.18 0 bottom
R91  2K/NC  [SR0603]  111.84 45.82 90 bottom
R92  33  [SR0402]  28.83 34.24 0 bottom
R93  10  [SR0402]  49.53 65.99 135 bottom
R94  10  [SR0402]  50.17 66.63 135 bottom
R95  0  [SR0402]  20.13 74.05 90 bottom
R96  10  [SR0402]  54.1 65.99 45 bottom
R97  10  [SR0402]  53.47 66.63 45 bottom
R98  10K  [SR0402]  25.27 62.31 90 top
R99  11.3K  [SR0402]  108.89 61.21 270 top
R100  10K  [SR0402]  16.91 63.22 270 top
R101  14.7K  [SR0402]  90.28 25.61 0 top
R102  100K  [SR0402]  90.83 22.93 0 top
R103  1K  [SR0402]  46.36 30.88 180 bottom
R104  5.6K  [SR0402]  18.38 61.83 180 top
R105  26.1K  [SR0402]  15.86 63.23 270 top
R106  22K  [SR0402]  86.64 81.17 270 top
R107  1K  [SR0402]  44.65 30.35 180 bottom
R110  14.7K  [SR0402]  90.28 23.84 0 top
R118  100K  [SR0402]  30.43 63.18 90 top
R135  10K  [SR0402]  87.63 20.39 90 top
R136  10K  [SR0402]  86.61 20.39 270 top
R140  10K  [SR0402]  123.93 18.7 90 top
R144  4.7K  [SR0402]  25.95 65 0 top
R145  100K/NC  [SR0402]  105.51 75.83 0 bottom
R146  100K/NC  [SR0402]  99.05 75.82 180 bottom
R173  10K  [SR0402]  65.61 60.85 270 bottom
R176  47K  [SR0402]  104.15 25.47 90 top
R177  47K  [SR0402]  105.42 25.47 90 top
R178  75  [SR0402]  124.95 18.7 90 top
R179  10  [SR0603]  108.22 70.18 180 top
R183  470K  [SR0402]  94.49 70.43 0 top
R186  2K  [SR0402]  36.83 80.84 0 top
R187  2K  [SR0402]  41.25 80.82 0 top
R188  47K  [SR0402]  106.69 25.47 90 top
R189  47K  [SR0402]  98.17 25.47 90 top
R193  20K  [SR0402]  94.87 72.7 180 top
R194  20K  [SR0402]  111.21 75.41 270 top
R202  47K  [SR0402]  107.96 25.47 90 top
R203  47K  [SR0402]  107.54 39.32 270 bottom
R212  10K  [SR0402]  102.97 41 90 bottom
R215  4.7K/NC  [SR0402]  100.35 44.63 0 bottom
R220  10K  [SR0402]  90.65 78.43 0 bottom
R268  27K  [SR0402]  36.01 76.3 0 top
R269  75  [SR0805]  53.59 77.93 90 bottom
R270  75  [SR0805]  51.82 77.93 90 bottom
R271  75  [SR0805]  48.26 77.93 90 bottom
R272  75  [SR0805]  50.04 77.93 90 bottom
RN1  33  [SRN8-0804]  28.83 50.62 270 top
RN2  33  [SRN8-0804]  28.83 54.56 270 top
RN3  33  [SRN8-0804]  28.83 45.54 270 top
RN4  33  [SRN8-0804]  28.83 39.96 270 top
RN5  33  [SRN8-0804]  28.83 42.75 270 top
RN6  33  [SRN8-0804]  28.83 36.02 270 top
RN7  33  [SRN8-0804]  28.83 57.36 270 top
RN8  33  [SRN8-0804]  28.83 36.02 270 bottom
RN9  33  [SRN8-0804]  28.83 50.62 270 bottom
RN10  33  [SRN8-0804]  28.83 42.75 270 bottom
RN11  33  [SRN8-0804]  28.83 54.56 270 bottom
RN12  33  [SRN8-0804]  28.83 45.54 270 bottom
RN13  33  [SRN8-0804]  28.83 39.96 270 bottom
RN14  33  [SRN8-0804]  28.83 57.36 270 bottom
S1  LS12T2_T  [RSTSW5-R]  74.58 91.76 180 top
S2  TMG_533_T_R  [SPSW6-T]  122.28 64.68 90 top
T2  H1102T  [STFM16-50-285]  51.82 74.15 0 top
U1  HI3798MV100  [LQFP216-040-2424]  71.22 48.1 0 top
U2  NC  [CDTWIFI]  8.86 31.62 90 top
U3  H5TQ4G63MFR_PBC_A  [BGA96-32-1609I]  47.25 51.95 180 top
U4  CS0806U  [SOT23A-6L]  37.67 78.58 270 top
U5  DIO2103_SGM8903  [SGM8903]  102.5 75.2 270 top
U6  H5TQ4G63MFR_PBC_A  [BGA96-32-1609I]  47.25 35.54 180 top
U7  NC  [CDTWIFI10]  8.48 31.62 90 top
U8  NC  [RN8-0402]  54.23 63.19 270 bottom
U11  SY8032  [SOT23_6]  107.51 58.33 270 top
U13  SY8032  [SOT23_6]  87.46 24.84 180 top
U14  MP1484_ETA1486  [SOIC8N]  19.27 69 180 top
U15  SY8089A_ETA3409  [SOT23_5]  7.75 55.82 90 top
U19  NC  [SOP48-20-720B]  104.01 37.9 180 top
U22  EMMC  [BGA169-BGA153-0_5MM]  104.01 37.9 90 top
U23  CS0806S  [DFN2510P10E]  27.51 80.66 0 top
U24  CS0806S  [DFN2510P10E]  30.68 80.66 0 top
U26  ETA6010  [SOT23-5]  87.05 77.92 90 top
X2  24MHZ  [X288]  92.33 40.91 90 top

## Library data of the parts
C1 C5 C8 C12 C14 C16-C19 C24 C28 C30 C34 C38 C41-C46 C48-C57 C59 C62-C70 C73-C85 C88 C89 C92-C99 C101-C109 C112 C115 C117-C119 C121-C133 C136-C138 C140 C142 C143 C149 C150 C153 C154 C158 C177 C182 C185 C186 C189 C193 C197-C199 C203 C206-C208 C211-C216 C218-C220 C222 C223 C227-C240 C243 C245 C258 C264 C270 C271 C289 C297 C307 C308 C310 C313 C314 C316 C317 C323 C324 C328 C330 C334 C336 C339 C364 C365 D4-D7 = SC0402
C2 C4 C25-C27 C111 C114 C372 = SC0805
C3 C6 C7 C9-C11 C13 C15 C20 C35-C37 C39 C40 C47 C61 C71 C72 C90 C91 C100 C110 C113 C116 C257 C265 C281-C283 C315 C319 C320 C350 C351 C363 C377 = SC0603
C21 C29 C58 C60 = SAC6666
C22 C23 C86 C87 = SC1206
C31-C33 C120 C242 C248 C250 C255 = HSC0402
C164 = SC0402: signal model: SC0402_10PF/NC
D1 D2 D19 D20 = HSOD323A
D3 = SEN3-100C
D9 Q1 Q2 Q4 Q13 Q14 = SOT23
ID1-ID6 = ID-BOARD
J1 = PWC3-RF-A
J2 = SIP12-2_0MM-1827
J3 = SIP5-2MM
J4 J6 = SIP-1P
J5 = SIP-2P
J7 J12 = USB4-200-1907
J8 J9 = HSCOX-AMC-TM-A
J10 = DC-002
J18 = WBC0104-49T
J25 = MJ8-RLY
J26 = WBC0119-20R-A
J34 = AV3-8-5-1
L1 L6 L7 LB1 LB3 LB5 LB6 LB12 LB31 = SL0402
L2-L4 = SWPA4020S
L5 = SWPA5040S
LB2 LB7 LB8 LB14 LB17 LB20-LB22 = SL0603
LB4 = SL0805
LED1 = LED3C-100C
M20 M21 = HOLE182-142
R1 R19 R20 R27 R28 R91 R179 = SR0603
R2-R18 R21-R26 R30-R35 R39-R44 R47-R53 R56 R57 R59-R71 R73 R75-R80 R82 R84 R85 R87-R90 R92-R97 R99-R107 R110 R118 R145 R146 R173 R176 R177 R183 R186-R189 R193 R194 R202 R203 R212 R220 R268 = SR0402
R29 R178 = SR0402: signal model: SR0402_75
R36-R38 R45 R46 = SR0402: signal model: SR0402_33
R54 R55 = SR0402: signal model: SR0402_240
R58 R98 R135 R136 R140 = SR0402: signal model: SR0402_10K
R72 R74 = HSR0402
R81 = SR1206: signal model: DEFAULT_RESISTOR_2.7OHM_1_2
R83 R269-R272 = SR0805
R144 R215 = SR0402: signal model: SR0402_4.7K
RN1-RN14 = SRN8-0804
S1 = RSTSW5-R
S2 = SPSW6-T
T2 = STFM16-50-285
U1 = LQFP216-040-2424
U2 = CDTWIFI
U3 U6 = BGA96-32-1609I
U4 = SOT23A-6L
U5 = SGM8903
U7 = CDTWIFI10
U8 = RN8-0402
U11 U13 = SOT23_6
U14 = SOIC8N
U15 = SOT23_5
U19 = SOP48-20-720B
U22 = BGA169-BGA153-0_5MM
U23 U24 = DFN2510P10E
U26 = SOT23-5
X2 = X288

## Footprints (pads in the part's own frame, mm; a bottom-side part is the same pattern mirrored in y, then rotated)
AV3-8-5-1
  oval 2.997x2.21 hole 2.997x2.21 unplated: (-4.45,10.8) (-4.45,-10.8)
  oval 2.997x2.007 hole 2.997x2.007 unplated: (-0.95,19.4) (-0.95,-19.4)
  round 1.803 hole 1.803 unplated: (3.05,7.5) (3.05,-7.5)
  rect 3.81x2.311 hole 2.489x1.194: 1(3.25,-15) 2(3.25,0) 3(3.25,15)
  rect 2.489x3.81 hole 1.499x2.489: 6(-0.75,-15) 7(-0.75,0) 8(-0.75,15)
BGA96-32-1609I
  round 0.356 smd: A1(-6,-3.2) A2(-6,-2.4) A3(-6,-1.6) A7(-6,1.6) A8(-6,2.4) A9(-6,3.2) B1(-5.2,-3.2) B2(-5.2,-2.4) B3(-5.2,-1.6) B7(-5.2,1.6) B8(-5.2,2.4) B9(-5.2,3.2) C1(-4.4,-3.2) C2(-4.4,-2.4) C3(-4.4,-1.6) C7(-4.4,1.6) C8(-4.4,2.4) C9(-4.4,3.2) D1(-3.6,-3.2) D2(-3.6,-2.4) D3(-3.6,-1.6) D7(-3.6,1.6) D8(-3.6,2.4) D9(-3.6,3.2) E1(-2.8,-3.2) E2(-2.8,-2.4) E3(-2.8,-1.6) E7(-2.8,1.6) E8(-2.8,2.4) E9(-2.8,3.2) F1(-2,-3.2) F2(-2,-2.4) F3(-2,-1.6) F7(-2,1.6) F8(-2,2.4) F9(-2,3.2) G1(-1.2,-3.2) G2(-1.2,-2.4) G3(-1.2,-1.6) G7(-1.2,1.6) G8(-1.2,2.4) G9(-1.2,3.2) H1(-0.4,-3.2) H2(-0.4,-2.4) H3(-0.4,-1.6) H7(-0.4,1.6) H8(-0.4,2.4) H9(-0.4,3.2) J1(0.4,-3.2) J2(0.4,-2.4) J3(0.4,-1.6) J7(0.4,1.6) J8(0.4,2.4) J9(0.4,3.2) K1(1.2,-3.2) K2(1.2,-2.4) K3(1.2,-1.6) K7(1.2,1.6) K8(1.2,2.4) K9(1.2,3.2) L1(2,-3.2) L2(2,-2.4) L3(2,-1.6) L7(2,1.6) L8(2,2.4) L9(2,3.2) M1(2.8,-3.2) M2(2.8,-2.4) M3(2.8,-1.6) M7(2.8,1.6) M8(2.8,2.4) M9(2.8,3.2) N1(3.6,-3.2) N2(3.6,-2.4) N3(3.6,-1.6) N7(3.6,1.6) N8(3.6,2.4) N9(3.6,3.2) P1(4.4,-3.2) P2(4.4,-2.4) P3(4.4,-1.6) P7(4.4,1.6) P8(4.4,2.4) P9(4.4,3.2) R1(5.2,-3.2) R2(5.2,-2.4) R3(5.2,-1.6) R7(5.2,1.6) R8(5.2,2.4) R9(5.2,3.2) T1(6,-3.2) T2(6,-2.4) T3(6,-1.6) T7(6,1.6) T8(6,2.4) T9(6,3.2)
BGA169-BGA153-0_5MM
  round 0.254 smd: A4(-6.75,-1.75) A6(-6.75,-0.75) A9(-6.75,0.75) A11(-6.75,1.75) AA2(3.25,-2.75) AA3(3.25,-2.25) AA4(3.25,-1.75) AA5(3.25,-1.25) AA6(3.25,-0.75) AA7(3.25,-0.25) AA8(3.25,0.25) AA9(3.25,0.75) AA10(3.25,1.25) AA11(3.25,1.75) AA12(3.25,2.25) AA13(3.25,2.75) AA14(3.25,3.25) AE1(5.25,-3.25) AE14(5.25,3.25) AG2(6.25,-2.75) AG13(6.25,2.75) AH4(6.75,-1.75) AH6(6.75,-0.75) AH9(6.75,0.75) AH11(6.75,1.75) B2(-6.25,-2.75) B13(-6.25,2.75) D1(-5.25,-3.25) D14(-5.25,3.25) H8(-3.25,0.25) H9(-3.25,0.75) H10(-3.25,1.25) H11(-3.25,1.75) H12(-3.25,2.25) H13(-3.25,2.75) H14(-3.25,3.25) J2(-2.75,-2.75) J3(-2.75,-2.25) J4(-2.75,-1.75) J5(-2.75,-1.25) J6(-2.75,-0.75) J7(-2.75,-0.25) J8(-2.75,0.25) J9(-2.75,0.75) J10(-2.75,1.25) J11(-2.75,1.75) J12(-2.75,2.25) J13(-2.75,2.75) J14(-2.75,3.25) K2(-2.25,-2.75) K3(-2.25,-2.25) K4(-2.25,-1.75) K5(-2.25,-1.25) K6(-2.25,-0.75) K7(-2.25,-0.25) K8(-2.25,0.25) K9(-2.25,0.75) K10(-2.25,1.25) K11(-2.25,1.75) K12(-2.25,2.25) K13(-2.25,2.75) K14(-2.25,3.25) L2(-1.75,-2.75) L3(-1.75,-2.25) L4(-1.75,-1.75) L12(-1.75,2.25) L13(-1.75,2.75) L14(-1.75,3.25) M1(-1.25,-3.25) M2(-1.25,-2.75) M3(-1.25,-2.25) M5(-1.25,-1.25) M6(-1.25,-0.75) M7(-1.25,-0.25) M8(-1.25,0.25) M9(-1.25,0.75) M10(-1.25,1.25) M12(-1.25,2.25) M13(-1.25,2.75) M14(-1.25,3.25) N1(-0.75,-3.25) N2(-0.75,-2.75) N3(-0.75,-2.25) N5(-0.75,-1.25) N10(-0.75,1.25) N12(-0.75,2.25) N13(-0.75,2.75) N14(-0.75,3.25) P1(-0.25,-3.25) P2(-0.25,-2.75) P3(-0.25,-2.25) P5(-0.25,-1.25) P10(-0.25,1.25) P12(-0.25,2.25) P13(-0.25,2.75) P14(-0.25,3.25) R1(0.25,-3.25) R2(0.25,-2.75) R3(0.25,-2.25) R5(0.25,-1.25) R10(0.25,1.25) R12(0.25,2.25) R13(0.25,2.75) R14(0.25,3.25) T1(0.75,-3.25) T2(0.75,-2.75) T3(0.75,-2.25) T5(0.75,-1.25) T10(0.75,1.25) T12(0.75,2.25) T13(0.75,2.75) T14(0.75,3.25) U1(1.25,-3.25) U2(1.25,-2.75) U3(1.25,-2.25) U5(1.25,-1.25) U6(1.25,-0.75) U7(1.25,-0.25) U8(1.25,0.25) U9(1.25,0.75) U10(1.25,1.25) U12(1.25,2.25) U13(1.25,2.75) U14(1.25,3.25) V1(1.75,-3.25) V2(1.75,-2.75) V3(1.75,-2.25) V12(1.75,2.25) V13(1.75,2.75) V14(1.75,3.25) W1(2.25,-3.25) W2(2.25,-2.75) W3(2.25,-2.25) W4(2.25,-1.75) W5(2.25,-1.25) W6(2.25,-0.75) W7(2.25,-0.25) W8(2.25,0.25) W9(2.25,0.75) W10(2.25,1.25) W11(2.25,1.75) W12(2.25,2.25) W13(2.25,2.75) W14(2.25,3.25) Y2(2.75,-2.75) Y3(2.75,-2.25) Y4(2.75,-1.75) Y5(2.75,-1.25) Y6(2.75,-0.75) Y7(2.75,-0.25) Y8(2.75,0.25) Y9(2.75,0.75) Y10(2.75,1.25) Y11(2.75,1.75) Y12(2.75,2.25) Y13(2.75,2.75) Y14(2.75,3.25)
  oval 0.203x0.254 smd: AA1(3.25,-3.25) H1(-3.25,-3.25) J1(-2.75,-3.25) K1(-2.25,-3.25) L1(-1.75,-3.25) Y1(2.75,-3.25)
  oval 0.254x0.203 smd: H2(-3.25,-2.75) H3(-3.25,-2.25) H4(-3.25,-1.75) H5(-3.25,-1.25) H6(-3.25,-0.75) H7(-3.25,-0.25)
CDTWIFI
  rect 1.981x1.524 smd: 1(6.087,4.005) 5(6.087,-4.795)
  rect 1.981x1.321 smd: 2(6.087,1.505) 4(6.087,-1.995)
  rect 2.184x1.27 smd: 3(6.189,-0.245)
  rect 2.489x1.397 smd: 6(-6.341,4.5) 7(-6.341,2.5)
CDTWIFI10
  oval 2.54x1.397 smd: 1(-6.1,4.121) 2(-6.1,2.121) 3(-6.1,-0.856) 4(-6.1,-3.015)
  oval 2.032x1.397 smd: 5(6.1,3.621) 6(6.1,1.121) 7(6.1,-2.379) 8(6.1,-5.179)
  oval 1.397x2.54 smd: 9(3.654,-6.5) 10(2.384,-6.5)
DC-002
  oval 2.997x1.803 hole 1.524x0.813: 1(0,0) 2(0,5)
  oval 1.803x2.997 hole 0.813x1.524: 3(-2.7,2.8)
DFN2510P10E
  oval 0.254x0.813 smd: 1(-1,-0.525) 5(1,-0.525) 6(1,0.525) 10(-1,0.525)
  oval 0.229x0.813 smd: 2(-0.5,-0.525) 4(0.5,-0.525) 7(0.5,0.525) 9(-0.5,0.525)
  oval 0.356x0.813 smd: 3(0,-0.525) 8(0,0.525)
HOLE182-142
  round 4.623 hole 3.607: 1(0,0)
HSC0402
  rect 0.508x0.508 smd: 1(-0.406,0) 2(0.406,0)
HSCOX-AMC-TM-A
  rect 0.813x0.813 smd: 1(0,1.35)
  rect 1.168x2.184 smd: 2(-1.326,0) 3(1.326,0)
HSOD323A
  rect 1.118x0.508 smd: 1(1.372,0) 2(-1.372,0)
HSR0402
  rect 0.508x0.508 smd: 1(-0.406,0) 2(0.406,0)
ID-BOARD
  round 1.016 smd: 1(0,0)
LED3C-100C
  rect 1.524x1.524 hole 0.965: 1(0,0)
  round 1.524 hole 0.965: 2(2.54,0) 3(5.08,0)
LQFP216-040-2424
  rect 0.305x1.397 smd: 1(-10.65,-12.71) 54(10.65,-12.71) 109(10.65,12.71) 162(-10.65,12.71)
  rect 0.203x1.397 smd: 2(-10.2,-12.71) 3(-9.8,-12.71) 4(-9.4,-12.71) 5(-9,-12.71) 6(-8.6,-12.71) 7(-8.2,-12.71) 8(-7.8,-12.71) 9(-7.4,-12.71) 10(-7,-12.71) 11(-6.6,-12.71) 12(-6.2,-12.71) 13(-5.8,-12.71) 14(-5.4,-12.71) 15(-5,-12.71) 16(-4.6,-12.71) 17(-4.2,-12.71) 18(-3.8,-12.71) 19(-3.4,-12.71) 20(-3,-12.71) 21(-2.6,-12.71) 22(-2.2,-12.71) 23(-1.8,-12.71) 24(-1.4,-12.71) 25(-1,-12.71) 26(-0.6,-12.71) 27(-0.2,-12.71) 28(0.2,-12.71) 29(0.6,-12.71) 30(1,-12.71) 31(1.4,-12.71) 32(1.8,-12.71) 33(2.2,-12.71) 34(2.6,-12.71) 35(3,-12.71) 36(3.4,-12.71) 37(3.8,-12.71) 38(4.2,-12.71) 39(4.6,-12.71) 40(5,-12.71) 41(5.4,-12.71) 42(5.8,-12.71) 43(6.2,-12.71) 44(6.6,-12.71) 45(7,-12.71) 46(7.4,-12.71) 47(7.8,-12.71) 48(8.2,-12.71) 49(8.6,-12.71) 50(9,-12.71) 51(9.4,-12.71) 52(9.8,-12.71) 53(10.2,-12.71) 110(10.2,12.71) 111(9.8,12.71) 112(9.4,12.71) 113(9,12.71) 114(8.6,12.71) 115(8.2,12.71) 116(7.8,12.71) 117(7.4,12.71) 118(7,12.71) 119(6.6,12.71) 120(6.2,12.71) 121(5.8,12.71) 122(5.4,12.71) 123(5,12.71) 124(4.6,12.71) 125(4.2,12.71) 126(3.8,12.71) 127(3.4,12.71) 128(3,12.71) 129(2.6,12.71) 130(2.2,12.71) 131(1.8,12.71) 132(1.4,12.71) 133(1,12.71) 134(0.6,12.71) 135(0.2,12.71) 136(-0.2,12.71) 137(-0.6,12.71) 138(-1,12.71) 139(-1.4,12.71) 140(-1.8,12.71) 141(-2.2,12.71) 142(-2.6,12.71) 143(-3,12.71) 144(-3.4,12.71) 145(-3.8,12.71) 146(-4.2,12.71) 147(-4.6,12.71) 148(-5,12.71) 149(-5.4,12.71) 150(-5.8,12.71) 151(-6.2,12.71) 152(-6.6,12.71) 153(-7,12.71) 154(-7.4,12.71) 155(-7.8,12.71) 156(-8.2,12.71) 157(-8.6,12.71) 158(-9,12.71) 159(-9.4,12.71) 160(-9.8,12.71) 161(-10.2,12.71)
  rect 1.397x0.305 smd: 55(12.71,-10.65) 108(12.71,10.65) 163(-12.71,10.65) 216(-12.71,-10.65)
  rect 1.397x0.203 smd: 56(12.71,-10.2) 57(12.71,-9.8) 58(12.71,-9.4) 59(12.71,-9) 60(12.71,-8.6) 61(12.71,-8.2) 62(12.71,-7.8) 63(12.71,-7.4) 64(12.71,-7) 65(12.71,-6.6) 66(12.71,-6.2) 67(12.71,-5.8) 68(12.71,-5.4) 69(12.71,-5) 70(12.71,-4.6) 71(12.71,-4.2) 72(12.71,-3.8) 73(12.71,-3.4) 74(12.71,-3) 75(12.71,-2.6) 76(12.71,-2.2) 77(12.71,-1.8) 78(12.71,-1.4) 79(12.71,-1) 80(12.71,-0.6) 81(12.71,-0.2) 82(12.71,0.2) 83(12.71,0.6) 84(12.71,1) 85(12.71,1.4) 86(12.71,1.8) 87(12.71,2.2) 88(12.71,2.6) 89(12.71,3) 90(12.71,3.4) 91(12.71,3.8) 92(12.71,4.2) 93(12.71,4.6) 94(12.71,5) 95(12.71,5.4) 96(12.71,5.8) 97(12.71,6.2) 98(12.71,6.6) 99(12.71,7) 100(12.71,7.4) 101(12.71,7.8) 102(12.71,8.2) 103(12.71,8.6) 104(12.71,9) 105(12.71,9.4) 106(12.71,9.8) 107(12.71,10.2) 164(-12.71,10.2) 165(-12.71,9.8) 166(-12.71,9.4) 167(-12.71,9) 168(-12.71,8.6) 169(-12.71,8.2) 170(-12.71,7.8) 171(-12.71,7.4) 172(-12.71,7) 173(-12.71,6.6) 174(-12.71,6.2) 175(-12.71,5.8) 176(-12.71,5.4) 177(-12.71,5) 178(-12.71,4.6) 179(-12.71,4.2) 180(-12.71,3.8) 181(-12.71,3.4) 182(-12.71,3) 183(-12.71,2.6) 184(-12.71,2.2) 185(-12.71,1.8) 186(-12.71,1.4) 187(-12.71,1) 188(-12.71,0.6) 189(-12.71,0.2) 190(-12.71,-0.2) 191(-12.71,-0.6) 192(-12.71,-1) 193(-12.71,-1.4) 194(-12.71,-1.8) 195(-12.71,-2.2) 196(-12.71,-2.6) 197(-12.71,-3) 198(-12.71,-3.4) 199(-12.71,-3.8) 200(-12.71,-4.2) 201(-12.71,-4.6) 202(-12.71,-5) 203(-12.71,-5.4) 204(-12.71,-5.8) 205(-12.71,-6.2) 206(-12.71,-6.6) 207(-12.71,-7) 208(-12.71,-7.4) 209(-12.71,-7.8) 210(-12.71,-8.2) 211(-12.71,-8.6) 212(-12.71,-9) 213(-12.71,-9.4) 214(-12.71,-9.8) 215(-12.71,-10.2)
  rect 8.382x8.382 smd: 217(0,0)
MJ8-RLY
  round 3.429 hole 3.429 unplated: (-2.794,2.54) (9.906,2.54)
  round 1.27 hole 0.914: 1(0,0) 2(1.016,-1.778) 3(2.032,0) 4(3.048,-1.778) 5(4.064,0) 6(5.08,-1.778) 7(6.096,0) 8(7.112,-1.778) 9(-3.302,-6.604) 10(-1.016,-6.604) 11(8.128,-6.604) 12(10.414,-6.604)
PWC3-RF-A
  rect 1.778x3.962 hole 0.762x2.946: 1(0,0)
  oval 3.454x1.778 hole 2.438x0.762: 2(2.3,4.8)
  oval 1.676x3.454 hole 0.66x2.438: 3(5.8,0)
RN8-0402
  rect 0.305x0.559 smd: 1(-0.762,-0.483) 4(0.762,-0.483) 5(0.762,0.483) 8(-0.762,0.483)
  rect 0.254x0.559 smd: 2(-0.254,-0.483) 3(0.254,-0.483) 6(0.254,0.483) 7(-0.254,0.483)
RSTSW5-R
  rect 0.711x1.118 smd: 1(-1.4,0.925) 2(1.4,0.925)
  rect 1.397x1.118 smd: 3(0,1.075)
  round 0.965 hole 0.559: 4(-1.825,-0.425) 5(1.825,-0.425)
  rect 1.143x0.66 smd: 6(-1.725,-1.05) 7(1.725,-1.05)
SAC6666
  rect 3.175x1.016 smd: 1(-2.5,0) 2(2.5,0)
SC0402
  rect 0.508x0.508 smd: 1(-0.406,0) 2(0.406,0)
SC0603
  rect 0.762x0.813 smd: 1(-0.699,0) 2(0.699,0)
SC0805
  rect 0.991x1.27 smd: 1(-0.813,0) 2(0.813,0)
SC1206
  rect 1.295x1.651 smd: 1(-1.346,0) 2(1.346,0)
SEN3-100C
  rect 1.27x1.27 hole 0.813: 1(-2.54,0)
  round 1.27 hole 0.813: 2(0,0) 3(2.54,0)
SGM8903
  rect 0.356x1.524 smd: 1(-1.95,-2.921) 2(-1.3,-2.921) 3(-0.65,-2.921) 4(0,-2.921) 5(0.65,-2.921) 6(1.3,-2.921) 7(1.95,-2.921) 8(1.95,2.921) 9(1.3,2.921) 10(0.65,2.921) 11(0,2.921) 12(-0.65,2.921) 13(-1.3,2.921) 14(-1.95,2.921)
SIP5-2MM
  oval 1.168x1.778 hole 0.914: 1(0,0) 2(2,0) 3(4,0) 4(6,0) 5(8,0)
SIP12-2_0MM-1827
  oval 3.175x1.524 hole 1.016: 1(-13.5,5.005) 2(-13.5,3.005) 3(-13.5,1.005) 4(-13.5,-0.995) 5(-13.5,-2.995) 6(-13.5,-4.995)
  oval 2.032x1.27 hole 1.016: 7(13.5,-5.604) 8(13.5,-4.104) 9(13.5,-2.604) 10(13.5,2.681) 11(13.5,4.181) 12(13.5,5.681)
SIP-1P
  round 1.651 hole 0.914: 1(0,0)
SIP-2P
  rect 1.524x1.524 hole 1.143: 1(-1.27,0)
  round 1.524 hole 1.143: 2(1.27,0)
SL0402
  rect 0.483x0.508 smd: 1(-0.394,0) 2(0.394,0)
SL0603
  rect 0.711x0.813 smd: 1(-0.74,0) 2(0.74,0)
SL0805
  rect 0.94x1.27 smd: 1(-0.851,0) 2(0.851,0)
SOIC8N
  rect 0.635x1.905 smd: 1(-1.905,-2.6) 2(-0.635,-2.6) 3(0.635,-2.6) 4(1.905,-2.6) 5(1.905,2.6) 6(0.635,2.6) 7(-0.635,2.6) 8(-1.905,2.6)
  rect 3.505x2.616 smd: 9(0,0)
SOP48-20-720B
  rect 0.254x1.473 smd: 1(-5.75,-9.802) 2(-5.25,-9.802) 3(-4.75,-9.802) 4(-4.25,-9.802) 5(-3.75,-9.802) 6(-3.25,-9.802) 7(-2.75,-9.802) 8(-2.25,-9.802) 9(-1.75,-9.802) 10(-1.25,-9.802) 11(-0.75,-9.802) 12(-0.25,-9.802) 13(0.25,-9.802) 14(0.75,-9.802) 15(1.25,-9.802) 16(1.75,-9.802) 17(2.25,-9.802) 18(2.75,-9.802) 19(3.25,-9.802) 20(3.75,-9.802) 21(4.25,-9.802) 22(4.75,-9.802) 23(5.25,-9.802) 24(5.75,-9.802) 25(5.75,9.802) 26(5.25,9.802) 27(4.75,9.802) 28(4.25,9.802) 29(3.75,9.802) 30(3.25,9.802) 31(2.75,9.802) 32(2.25,9.802) 33(1.75,9.802) 34(1.25,9.802) 35(0.75,9.802) 36(0.25,9.802) 37(-0.25,9.802) 38(-0.75,9.802) 39(-1.25,9.802) 40(-1.75,9.802) 41(-2.25,9.802) 42(-2.75,9.802) 43(-3.25,9.802) 44(-3.75,9.802) 45(-4.25,9.802) 46(-4.75,9.802) 47(-5.25,9.802) 48(-5.75,9.802)
SOT23
  rect 1.016x1.27 smd: 1(-1.016,-1.143) 2(1.016,-1.143) 3(0,1.143)
SOT23-5
  rect 0.711x1.016 smd: 1(-0.95,-1.3) 2(0,-1.3) 3(0.95,-1.3) 4(0.95,1.3) 5(-0.95,1.3)
SOT23_5
  rect 0.635x1.27 smd: 1(-0.95,-1.2) 2(0,-1.2) 3(0.95,-1.2) 4(0.95,1.2) 5(-0.95,1.2)
SOT23_6
  rect 0.635x1.397 smd: 1(-0.95,-1.2) 2(0,-1.2) 3(0.95,-1.2) 4(0.95,1.2) 5(0,1.2) 6(-0.95,1.2)
SOT23A-6L
  rect 0.635x1.27 smd: 1(-0.95,-1.25) 2(0,-1.25) 3(0.95,-1.25) 4(0.95,1.25) 5(0,1.25) 6(-0.95,1.25)
SPSW6-T
  rect 1.829x1.118 smd: 1(-3.1,1.85) 2(3.1,1.85) 3(-3.1,-1.85) 4(3.1,-1.85)
  rect 1.397x0.61 smd: 5(0,2.5) 6(0,-2.5)
SR0402
  rect 0.508x0.508 smd: 1(-0.406,0) 2(0.406,0)
SR0603
  rect 0.711x0.813 smd: 1(-0.737,0) 2(0.737,0)
SR0805
  rect 0.838x1.143 smd: 1(-0.927,0) 2(0.927,0)
SR1206
  rect 1.295x1.6 smd: 1(-1.346,0) 2(1.346,0)
SRN8-0804
  rect 0.279x0.533 smd: 1(-0.762,-0.521) 2(-0.254,-0.521) 3(0.254,-0.521) 4(0.762,-0.521) 5(0.762,0.521) 6(0.254,0.521) 7(-0.254,0.521) 8(-0.762,0.521)
STFM16-50-285
  rect 0.635x1.905 smd: 1(-4.445,-4.381) 2(-3.175,-4.381) 3(-1.905,-4.381) 4(-0.635,-4.381) 5(0.635,-4.381) 6(1.905,-4.381) 7(3.175,-4.381) 8(4.445,-4.381) 9(4.445,4.381) 10(3.175,4.381) 11(1.905,4.381) 12(0.635,4.381) 13(-0.635,4.381) 14(-1.905,4.381) 15(-3.175,4.381) 16(-4.445,4.381)
SWPA4020S
  rect 1.905x3.683 smd: 1(-1.55,0) 2(1.55,0)
SWPA5040S
  rect 1.397x4.191 smd: 1(-1.85,0) 2(1.85,0)
unnamed#2
  round 1.016 hole 1.016 unplated: (-3,1.13) (-1.5,1.13) (0,1.13) (1.5,1.13) (3,1.13)
USB4-200-1907
  oval 1.27x1.778 hole 0.914: 1(0,0) 2(2,0) 3(4,0) 4(6,0)
  round 2.032 hole 1.321: 5(-0.73,2.72) 6(6.27,2.72) 7(-0.73,-2.72) 8(6.27,-2.72)
WBC0104-49T
  oval 0.762x1.143 hole 0.508: 1(0,0) 2(1.25,0) 3(2.5,0) 4(3.75,0)
WBC0119-20R-A
  round 1.092 hole 1.092 unplated: (-2.5,2.745) (2.5,2.745)
  rect 0.254x2.591 smd: 1(4.5,5.155) 2(4,5.155) 3(3.5,5.155) 4(3,5.155) 5(2.5,5.155) 6(2,5.155) 7(1.5,5.155) 8(1,5.155) 9(0.5,5.155) 10(0,5.155) 11(-0.5,5.155) 12(-1,5.155) 13(-1.5,5.155) 14(-2,5.155) 15(-2.5,5.155) 16(-3,5.155) 17(-3.5,5.155) 18(-4,5.155) 19(-4.5,5.155)
  oval 1.524x3.302 hole 0.914x2.667: 20(-7.25,4.395) 21(7.25,4.395)
  oval 1.524x2.794 hole 0.914x2.083: 22(-7.25,-1.565) 23(7.25,-1.565)
X288
  rect 1.651x1.27 smd: 1(-1.15,-0.85) 2(1.15,-0.85) 3(1.15,0.85) 4(-1.15,0.85)

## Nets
1V1_CORE: C1.1 C19.1 C22.1 C37.1 C51.1 C62.1 C64.1 C66.1 C70.1 C73.1 C82.2 C87.1 C90.1 C107.1 C120.1 C121.1 C126.1 C127.1 C128.1 C129.1 C130.1 C189.1 C193.1 C282.1 L3.2 LB12.2 LB21.1 LB31.1 R101.2 U1.4 U1.10 U1.30 U1.39 U1.49 U1.78 U1.86 U1.105 U1.118 U1.134 U1.158 U1.168 U1.180 U1.186 U1.193 U1.202 U1.214
1V1_CPU: C16.1 C21.1 C31.1 C34.1 C35.1 C38.1 C41.1 C42.1 C75.1 C76.2 C81.1 C86.1 C116.1 C132.1 C242.1 C243.1 C257.1 L2.2 R53.2 U1.91 U1.92 U1.93 U1.95 U1.96 U1.98
1V5_DDR3: C20.1 C28.1 C40.1 C48.1 C49.1 C52.1 C68.1 C84.2 C92.1 C94.1 C96.1 C97.1 C98.1 C99.1 C101.1 C102.1 C104.1 C109.1 C110.1 C117.1 C125.1 C131.1 C133.1 C137.1 C203.1 C206.1 C207.1 C208.1 C211.1 C212.1 C213.1 C214.1 C215.1 C216.1 C218.1 C219.1 C220.1 C222.1 C223.1 C227.1 C228.1 C229.1 C230.1 C231.1 C232.1 C233.1 C234.1 C235.1 C236.1 C237.1 C238.1 C239.1 C240.1 C258.1 C315.1 C319.1 L4.2 R10.2 R51.1 R54.1 R60.1 R76.1 R78.1 R103.1 U1.1 U1.7 U1.13 U1.16 U1.25 U1.35 U1.44 U1.53 U1.165 U1.171 U1.174 U1.183 U1.190 U1.196 U1.199 U1.205 U1.208 U3.A1 U3.A8 U3.B2 U3.C1 U3.C9 U3.D2 U3.D9 U3.E9 U3.F1 U3.G7 U3.H2 U3.H9 U3.K2 U3.K8 U3.N1 U3.N9 U3.R1 U3.R9 U6.A1 U6.A8 U6.B2 U6.C1 U6.C9 U6.D2 U6.D9 U6.E9 U6.F1 U6.G7 U6.H2 U6.H9 U6.K2 U6.K8 U6.N1 U6.N9 U6.R1 U6.R9
3V3: C2.1 C4.1 C13.1 C25.1 C26.1 C27.1 C39.1 C46.1 C53.1 C67.1 C69.1 C91.1 C108.1 C114.1 J18.4 L5.2 LB5.1 Q13.2 R2.1 R6.1 R31.1 R34.1 R83.1 R88.2 R105.2 R135.1 R136.2 R140.2 R178.2 U11.4 U13.4 U15.4
3V3_IR: C47.1 C177.1 D3.3 J3.2 R178.1
3V3_MOS: C74.1 C197.1 C198.1 C199.1 C245.1 C283.1 D1.2 D9.2 D19.2 J25.10 J25.12 LB1.2 LB4.2 LB6.1 LB7.2 LB8.2 LB14.1 LB17.1 LB20.1 LB22.1 Q13.3 R25.1 R26.1 R30.1 R39.2 R41.2 U1.74 U1.83 U1.104 U1.120
3V3_MOS_FLASH: C29.1 C36.1 C63.1 C93.1 C100.1 C105.1 C142.1 C143.1 C323.1 C324.1 D1.1 LB6.2 R12.1 R29.1 R49.1 R57.2 R58.1 R91.1 R176.1 R177.1 R188.1 R189.1 R202.1 R203.1 R212.1 R215.1 U19.1 U19.12 U19.24 U19.34 U19.37 U22.AA3 U22.AA5 U22.K6 U22.M6 U22.N5 U22.T10 U22.U9 U22.W4 U22.Y4
3V3_WIFI: C15.1 C61.1 J2.5 LB4.1 U2.5 U7.8
5V0: C6.1 C58.1 C59.1 C111.1 C112.1 D2.2 J5.1 Q14.2 R4.1 R81.2 R144.1 U14.2
5V0_MOS: C377.1 D20.2 LB2.2 Q14.3 R179.1 R220.2 U26.1
5V0_MOS_HDMI: C150.1 D20.1 J26.18 R186.2 R187.2 U4.5
AVDD11_PLL012: C12.1 C185.1 LB21.2 U1.68
AVDD33_PLL01: C14.1 C186.1 LB22.2 U1.66
AVDD33_USB2: C3.1 C95.1 LB17.2 U1.88
GND: C1.2 C2.2 C3.2 C4.2 C5.2 C7.2 C8.2 C9.2 C10.2 C11.2 C12.2 C13.2 C14.2 C15.2 C16.2 C17.2 C18.2 C19.2 C20.2 C21.2 C22.2 C23.2 C24.2 C25.2 C26.2 C27.2 C28.2 C29.2 C30.2 C31.2 C33.1 C34.2 C35.2 C36.2 C37.2 C38.2 C39.2 C40.2 C41.2 C42.2 C43.2 C44.2 C45.2 C46.2 C47.2 C48.2 C49.2 C50.2 C51.2 C52.2 C53.2 C56.2 C57.2 C58.2 C59.2 C60.2 C61.2 C62.2 C63.2 C64.2 C66.2 C67.2 C68.2 C69.2 C70.2 C71.2 C72.2 C73.2 C74.2 C75.2 C77.2 C78.2 C79.2 C81.2 C85.2 C86.2 C87.2 C88.2 C89.2 C90.2 C91.2 C92.2 C93.2 C94.2 C95.2 C96.2 C97.2 C98.2 C99.2 C100.2 C101.2 C102.2 C103.2 C104.2 C105.2 C106.2 C107.2 C108.2 C109.2 C110.2 C111.2 C112.2 C113.2 C114.2 C115.2 C116.2 C117.2 C118.2 C119.2 C120.2 C121.2 C122.2 C123.2 C124.2 C125.2 C126.2 C127.2 C128.2 C129.2 C130.2 C131.2 C132.2 C133.2 C136.2 C137.2 C138.1 C140.2 C142.2 C143.2 C149.2 C150.2 C153.2 C154.2 C158.2 C164.2 C177.2 C182.2 C185.2 C186.2 C189.2 C193.2 C197.2 C198.2 C199.2 C203.2 C206.2 C211.2 C212.2 C213.2 C214.2 C215.2 C216.2 C218.2 C219.2 C220.2 C227.2 C228.2 C229.2 C230.2 C231.2 C232.2 C233.2 C234.2 C235.2 C236.2 C237.2 C238.2 C239.2 C240.2 C242.2 C243.2 C245.2 C248.2 C250.1 C255.1 C257.2 C258.2 C264.2 C265.2 C270.2 C271.2 C281.2 C282.2 C283.2 C289.2 C297.2 C307.2 C308.2 C310.2 C313.2 C314.2 C315.2 C316.2 C317.2 C319.2 C320.2 C323.2 C324.2 C328.2 C330.2 C334.2 C336.2 C339.2 C363.2 C364.2 C365.2 C372.2 C377.2 D3.2 D4.2 D5.2 D6.2 D7.2 D9.1 J1.2 J1.3 J2.2 J2.7 J2.9 J2.10 J2.12 J3.4 J4.1 J6.1 J7.4 J7.5 J7.6 J7.7 J7.8 J8.2 J8.3 J9.2 J9.3 J10.2 J10.3 J12.4 J12.5 J12.6 J12.7 J12.8 J18.1 J26.2 J26.5 J26.8 J26.11 J26.17 J26.20 J26.21 J26.22 J26.23 J34.6 J34.7 J34.8 LED1.2 Q1.2 Q2.2 Q4.2 R8.1 R9.2 R13.1 R24.1 R32.1 R33.2 R38.1 R40.2 R44.2 R45.2 R46.1 R50.2 R52.2 R55.2 R56.1 R71.1 R75.2 R77.2 R82.1 R83.2 R84.2 R85.1 R87.1 R89.2 R91.2 R99.1 R100.2 R104.2 R106.1 R107.2 R145.2 R146.2 R173.2 R183.2 RN1.3 RN1.6 RN2.3 RN2.6 RN3.2 RN3.7 RN4.3 RN4.6 RN5.2 RN5.7 RN6.3 RN6.6 RN7.2 RN7.7 RN8.3 RN8.6 RN9.3 RN9.6 RN10.2 RN10.7 RN11.3 RN11.6 RN12.2 RN12.7 RN13.3 RN13.6 RN14.2 RN14.7 S1.1 S1.3 S1.4 S1.5 S1.6 S1.7 S2.3 S2.4 S2.5 S2.6 U1.19 U1.62 U1.67 U1.94 U1.97 U1.110 U1.115 U1.177 U1.211 U1.217 U2.1 U2.6 U3.A9 U3.B1 U3.B3 U3.B9 U3.D1 U3.D8 U3.E1 U3.E2 U3.E8 U3.F9 U3.G1 U3.G8 U3.G9 U3.J2 U3.J8 U3.M1 U3.M9 U3.P1 U3.P9 U3.T1 U3.T9 U4.2 U5.1 U5.4 U5.10 U5.14 U6.A9 U6.B1 U6.B3 U6.B9 U6.D1 U6.D8 U6.E1 U6.E2 U6.E8 U6.F9 U6.G1 U6.G8 U6.G9 U6.J2 U6.J8 U6.M1 U6.M9 U6.P1 U6.P9 U6.T1 U6.T9 U7.1 U7.5 U11.2 U13.2 U14.4 U14.9 U15.2 U19.2 U19.13 U19.23 U19.25 U19.36 U19.48 U22.AA4 U22.AA6 U22.K4 U22.M7 U22.P5 U22.R10 U22.U8 U22.Y2 U22.Y5 U23.3 U23.8 U24.3 U24.8 U26.2 X2.2 X2.4
VDD_AUDIO: C158.1 C320.1 R48.1 R66.2 R179.2 U5.9
ADAC_VOUTL: C350.2 R50.1 U1.114
ADAC_VOUTR: C351.1 R183.1 U1.116
AUDIO_L: C339.1 J34.2 R72.2
AUDIO_R: C140.1 J34.1 R74.1
CORE_CTRL: R23.2 U1.106
CPU_CTRL: R21.2 U1.107
CVBS: C79.1 C80.1 L6.1 R9.1 U1.109
CVBS_OUT: C17.1 C80.2 D9.3 J34.3 L6.2
DDR_ADDR0: RN2.1 RN11.8 U1.43
DDR_ADDR0_A: RN2.8 U3.N3
DDR_ADDR0_B: RN11.1 U6.N3
DDR_ADDR1: RN4.4 RN13.5 U1.27
DDR_ADDR1_A: RN4.5 U3.P7
DDR_ADDR1_B: RN13.4 U6.P7
DDR_ADDR2: R62.1 R69.1 U1.45
DDR_ADDR2_A: R62.2 U3.P3
DDR_ADDR2_B: R69.2 U6.P3
DDR_ADDR3: RN2.2 RN11.7 U1.42
DDR_ADDR3_A: RN2.7 U3.N2
DDR_ADDR3_B: RN11.2 U6.N2
DDR_ADDR4: R64.1 R90.1 U1.26
DDR_ADDR4_A: R64.2 U3.P8
DDR_ADDR4_B: R90.2 U6.P8
DDR_ADDR5: RN2.4 RN11.5 U1.51
DDR_ADDR5_A: RN2.5 U3.P2
DDR_ADDR5_B: RN11.4 U6.P2
DDR_ADDR6: RN4.2 RN13.7 U1.28
DDR_ADDR6_A: RN4.7 U3.R8
DDR_ADDR6_B: RN13.2 U6.R8
DDR_ADDR7: R61.1 R68.1 U1.50
DDR_ADDR7_A: R61.2 U3.R2
DDR_ADDR7_B: R68.2 U6.R2
DDR_ADDR8: RN4.1 RN13.8 U1.29
DDR_ADDR8_A: RN4.8 U3.T8
DDR_ADDR8_B: RN13.1 U6.T8
DDR_ADDR9: RN1.2 RN9.7 U1.37
DDR_ADDR9_A: RN1.7 U3.R3
DDR_ADDR9_B: RN9.2 U6.R3
DDR_ADDR10: RN6.4 RN8.5 U1.22
DDR_ADDR10_A: RN6.5 U3.L7
DDR_ADDR10_B: RN8.4 U6.L7
DDR_ADDR11: RN5.3 RN10.6 U1.32
DDR_ADDR11_A: RN5.6 U3.R7
DDR_ADDR11_B: RN10.3 U6.R7
DDR_ADDR12: RN6.2 RN8.7 U1.23
DDR_ADDR12_A: RN6.7 U3.N7
DDR_ADDR12_B: RN8.2 U6.N7
DDR_ADDR13: RN1.4 RN9.5 U1.46
DDR_ADDR13_A: RN1.5 U3.T3
DDR_ADDR13_B: RN9.4 U6.T3
DDR_ADDR14: RN5.4 RN10.5 U1.31
DDR_ADDR14_A: RN5.5 U3.T7
DDR_ADDR14_B: RN10.4 U6.T7
DDR_ADDR15: RN5.1 RN10.8 U1.36
DDR_ADDR15_A: RN5.8 U3.M7
DDR_ADDR15_B: RN10.1 U6.M7
DDR_BA0: RN7.4 RN14.5 U1.47
DDR_BA0_A: RN7.5 U3.M2
DDR_BA0_B: RN14.4 U6.M2
DDR_BA1: RN6.1 RN8.8 U1.24
DDR_BA1_A: RN6.8 U3.N8
DDR_BA1_B: RN8.1 U6.N8
DDR_BA2: RN3.1 RN12.8 U1.33
DDR_BA2_A: RN3.8 U3.M3
DDR_BA2_B: RN12.1 U6.M3
DDR_CASN: RN3.4 RN12.5 U1.40
DDR_CASN_A: RN3.5 U3.K3
DDR_CASN_B: RN12.4 U6.K3
DDR_CKE: R38.2 R65.1 R92.1 U1.21
DDR_CKE_A: R65.2 U3.K9
DDR_CKE_B: R92.2 U6.K9
DDR_CLK0N: R11.1 R35.1 U3.K7
DDR_CLK0P: R15.2 R18.1 U3.J7
DDR_CLK1N: R16.1 R37.1 U6.K7
DDR_CLK1P: R17.2 R36.1 U6.J7
DDR_CSN: R63.1 R80.1 U1.34
DDR_CSN_A: R63.2 U3.L2
DDR_CSN_B: R80.2 U6.L2
DDR_DM0: U1.181 U3.E7
DDR_DM1: U1.182 U3.D3
DDR_DM2: U1.215 U6.E7
DDR_DM3: U1.216 U6.D3
DDR_DQ0: U1.167 U3.E3
DDR_DQ1: U1.191 U3.F7
DDR_DQ2: U1.164 U3.F2
DDR_DQ3: U1.192 U3.F8
DDR_DQ4: U1.166 U3.H3
DDR_DQ5: U1.195 U3.H8
DDR_DQ6: U1.163 U3.G2
DDR_DQ7: U1.194 U3.H7
DDR_DQ8: U1.184 U3.D7
DDR_DQ9: U1.170 U3.C3
DDR_DQ10: U1.185 U3.C8
DDR_DQ11: U1.169 U3.C2
DDR_DQ12: U1.188 U3.A7
DDR_DQ13: U1.172 U3.A2
DDR_DQ14: U1.189 U3.B8
DDR_DQ15: U1.173 U3.A3
DDR_DQ16: U1.201 U6.E3
DDR_DQ17: U1.8 U6.F7
DDR_DQ18: U1.198 U6.F2
DDR_DQ19: U1.9 U6.F8
DDR_DQ20: U1.200 U6.H3
DDR_DQ21: U1.12 U6.H8
DDR_DQ22: U1.197 U6.G2
DDR_DQ23: U1.11 U6.H7
DDR_DQ24: U1.6 U6.D7
DDR_DQ25: U1.204 U6.C3
DDR_DQ26: U1.5 U6.C8
DDR_DQ27: U1.203 U6.C2
DDR_DQ28: U1.2 U6.A7
DDR_DQ29: U1.206 U6.A2
DDR_DQ30: U1.3 U6.B8
DDR_DQ31: U1.207 U6.A3
DDR_DQS0N: U1.176 U3.G3
DDR_DQS0P: U1.175 U3.F3
DDR_DQS1N: U1.179 U3.B7
DDR_DQS1P: U1.178 U3.C7
DDR_DQS2N: U1.210 U6.G3
DDR_DQS2P: U1.209 U6.F3
DDR_DQS3N: U1.213 U6.B7
DDR_DQS3P: U1.212 U6.C7
DDR_ODT: RN7.3 RN14.6 U1.48
DDR_ODT_A: RN7.6 U3.K1
DDR_ODT_B: RN14.3 U6.K1
DDR_PLL: C11.1 C264.1 C270.1 LB7.1 U1.20 U1.187
DDR_RASN: RN7.1 RN14.8 U1.52
DDR_RASN_A: RN7.8 U3.J3
DDR_RASN_B: RN14.1 U6.J3
DDR_RESETN: RN1.1 RN9.8 U1.38
DDR_RESETN_A: C313.1 R60.2 RN1.8 U3.T2
DDR_RESETN_B: C314.1 R76.2 RN9.1 U6.T2
DDR_VREF_CA_A: C207.2 C289.1 R51.2 R55.1 U3.M8
DDR_VREF_CA_B: C222.2 C310.1 R103.2 R107.1 U6.M8
DDR_VREF_DQ_A: C208.2 C271.1 R54.2 R75.1 U3.H1
DDR_VREF_DQ_B: C223.2 C308.1 R78.2 R84.1 U6.H1
DDR_WEN: RN3.3 RN12.6 U1.41
DDR_WEN_A: RN3.6 U3.L3
DDR_WEN_B: RN12.3 U6.L3
FE_1V1: C248.1 U1.147
FE_3V3: C7.1 C18.1 LB8.1 U1.144 U1.148
HDMI_TX0N: J26.9 U1.126 U24.2 U24.9
HDMI_TX0P: J26.7 U1.127 U24.1 U24.10
HDMI_TX1N: J26.6 U1.130 U23.5 U23.6
HDMI_TX1P: J26.4 U1.131 U23.4 U23.7
HDMI_TX2N: J26.3 U1.132 U23.2 U23.9
HDMI_TX2P: J26.1 U1.133 U23.1 U23.10
HDMI_TX_1V1: C78.1 C113.1 C164.1 C281.1 LB12.1 U1.128
HDMI_TX_3V3: C57.1 C77.1 LB1.1 U1.129
HDMI_TX_CEC: J26.13 R268.2 U1.123 U4.3
HDMI_TX_HOTPLUG: C149.1 J26.19 R8.2 U1.119 U4.4
HDMI_TX_SCL: J26.15 R186.1 U1.122 U4.1
HDMI_TX_SDA: J26.16 R187.1 U1.121 U4.6
HDMI_TXCN: J26.12 U1.124 U24.5 U24.6
HDMI_TXCP: J26.10 U1.125 U24.4 U24.7
